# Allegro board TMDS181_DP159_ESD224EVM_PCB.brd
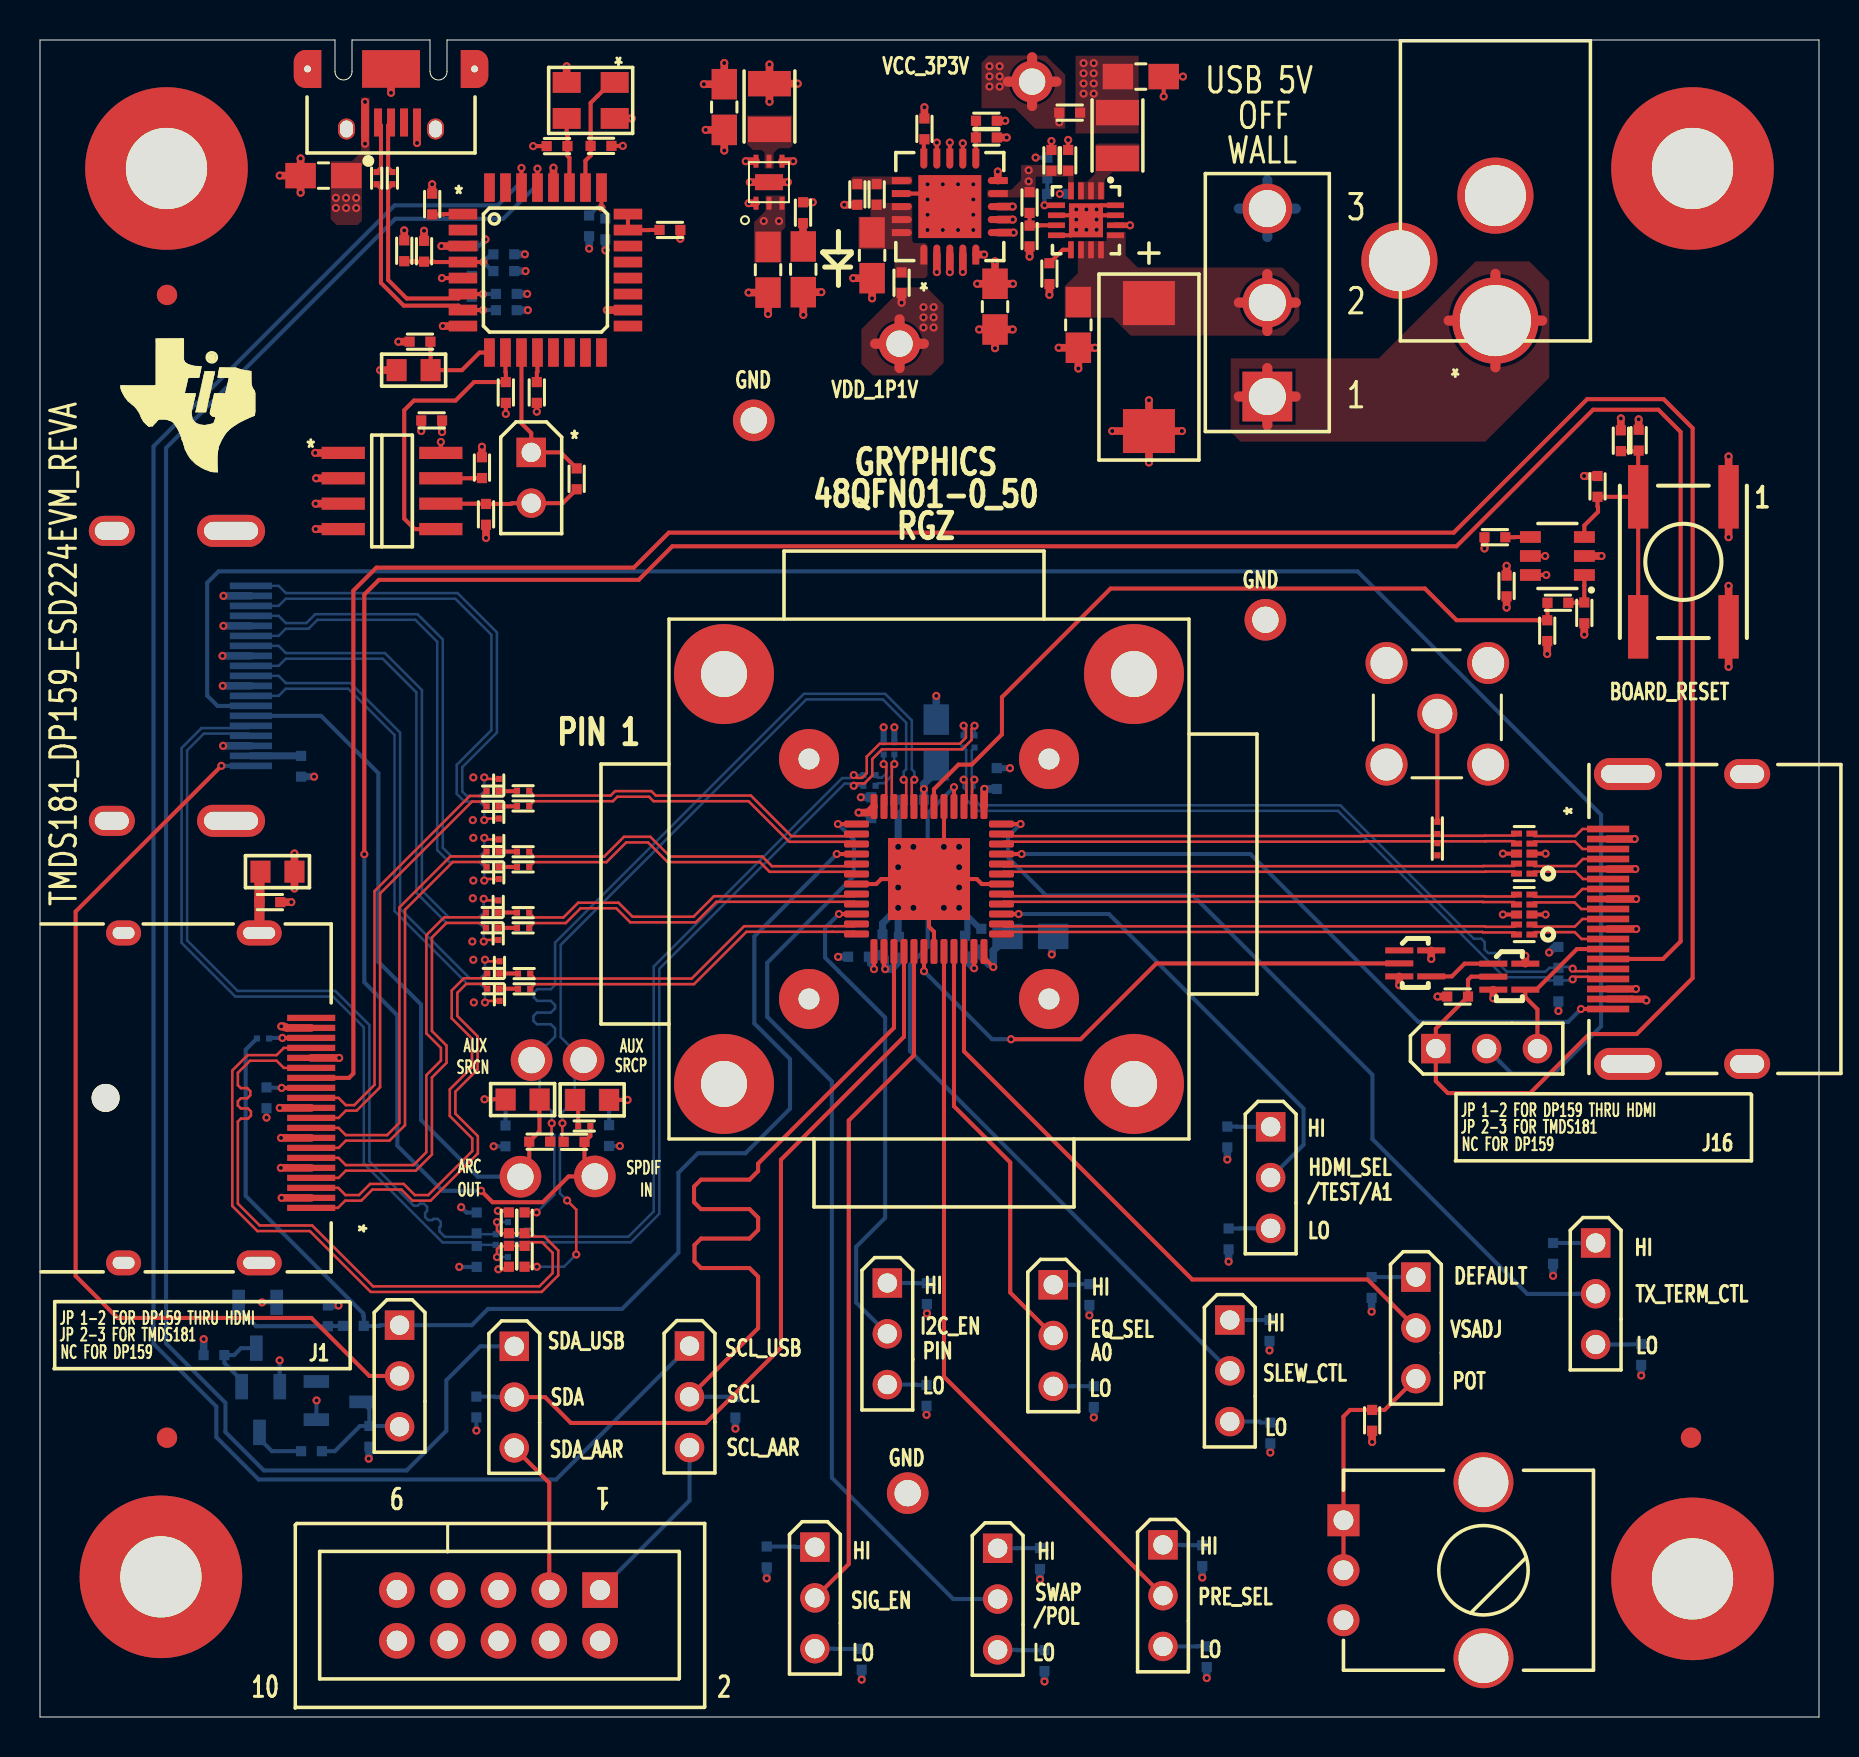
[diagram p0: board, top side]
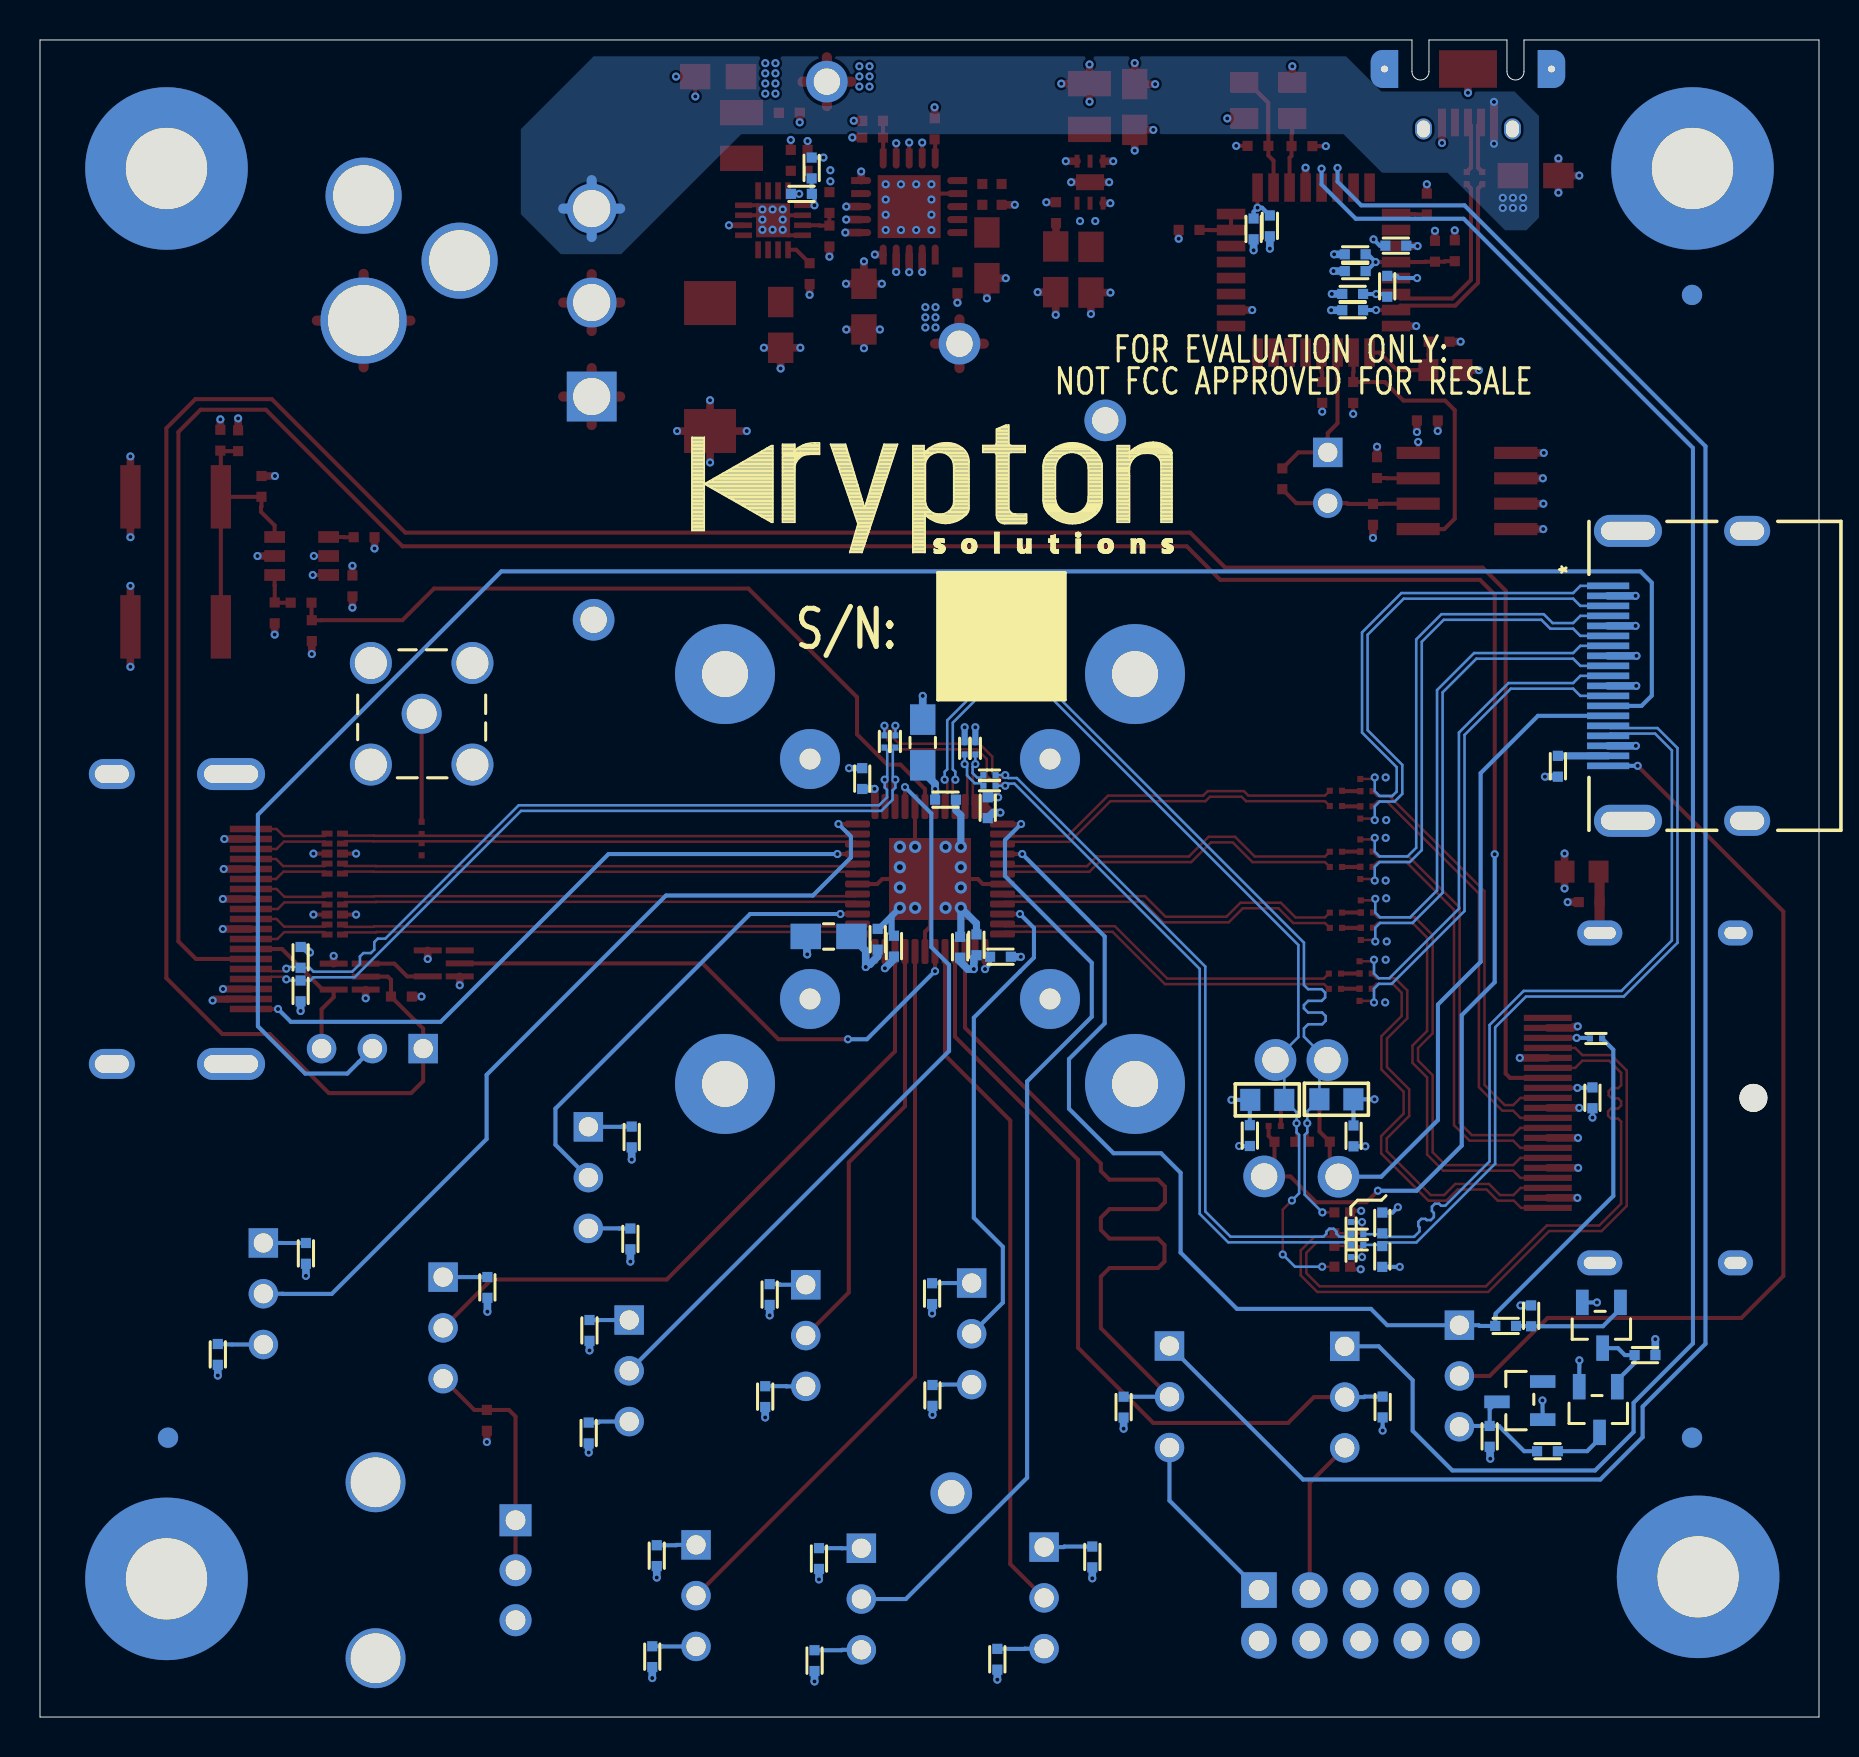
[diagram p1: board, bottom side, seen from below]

Outline 88.95 x 83.87 mm; copper layers: TOP, L2, L3, L4, L5, BOTTOM. Coordinates in mm from the lower left corner of the outline.
Outline path: 0,83.87 0,0 88.95,0 88.95,83.87 20.35,83.87 20.35,82.3 arc(19.93,81.87) 19.5,82.3 19.5,83.87 15.6,83.87 15.6,82.29 arc(15.18,81.87) 14.75,82.29 14.75,83.87 0,83.87

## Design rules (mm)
net group DIFFPAIR0: nets N16880319 N16880326
net group DIFFPAIR1: nets N16880333 N16880340
net group DIFFPAIR2: nets N16880347 N16880354
net group DIFFPAIR3: nets N16880361 N16880368
net group DIFFPAIR4: nets C_DPRX_LN3N C_DPRX_LN3P
net group DIFFPAIR5: nets C_DPRX_LN2N C_DPRX_LN2P
net group DIFFPAIR6: nets C_DPRX_LN1N C_DPRX_LN1P
net group DIFFPAIR7: nets C_DPRX_LN0N C_DPRX_LN0P
net group DIFFPAIR12: nets OUT_D2N OUT_D2P
net group DIFFPAIR13: nets OUT_D1N OUT_D1P
net group DIFFPAIR14: nets OUT_D0N OUT_D0P
net group DIFFPAIR15: nets OUT_CLKN OUT_CLKP
net group DIFFPAIR16: nets IN_D0N IN_D0P
net group DIFFPAIR17: nets IN_D1N IN_D1P
net group DIFFPAIR18: nets IN_D2N IN_D2P
net group DIFFPAIR19: nets IN_CLKN IN_CLKP
net group DIFFPAIR20: nets N16925972 N16925975
net group DIFFPAIR21: nets N16926008 N16926011
net group DIFFPAIR22: nets N16926002 N16926005
net group DIFFPAIR23: nets N16925996 N16925999
net group DIFFPAIR24: nets SCL_SRC SDA_SRC
net group DIFFPAIR25: nets HDMI_SCL_SRC HDMI_SDA_SRC
net group DIFFPAIR26: nets N16887471 N16913511
net group DIFFPAIR27: nets N16919318 N16919400
net group DIFFPAIR28: nets DP_SCL_SRC DP_SDA_SRC
net group DIFFPAIR29: nets AUX_SRCN/ARC_OUT AUX_SRCP/SPDIF_IN
net group DIFFPAIR30: nets SCL_SNK SDA_SNK
net group DIFFPAIR31: nets N17009600 N17009604
net group DIFFPAIR32: nets N17009637 N17009639
net group DIFFPAIR33: nets N17009633 N17009635
net group DIFFPAIR34: nets N17009643 N17009645
net group DIFF_PAIR 100 OHM_PH: nets EQ_SEL_A0 HDMI_SEL#_TEST_A1 I2C_EN_PIN OE PRE_SEL SCL_CTL_USB SDA_CTL_USB SIG_EN SLEW_CTL SWAP/POL TX_TERM_CTL VSADJ

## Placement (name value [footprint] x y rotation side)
C1  1 uF  [0603]  11.02 42.28 0 top
C2  0.1 uF  [0402]  24.23 24.72 270 top
C3  0.1 uF  [0402]  24.23 23.04 90 top
C4  1 uF  [0603]  24.98 30.89 180 bottom
C5  1 uF  [0603]  26.74 30.86 0 bottom
C6  1 uF  [0603]  24.98 30.88 180 top
C7  1 uF  [0603]  28.46 30.86 180 top
C8  10 uF  [0805]  44.81 48.74 90 bottom
C9  0.1 uF  [0402]  40.93 38.02 180 bottom
C10  0.1 uF  [0402]  43.67 45.88 180 bottom
C11  0.1 uF  [0201]  24.16 46.32 0 top
C12  0.1 uF  [0201]  24.16 45.56 0 top
C13  0.1 uF  [0201]  24.16 43.28 0 top
C14  0.1 uF  [0201]  24.16 42.51 0 top
C15  0.1 uF  [0201]  24.16 40.23 0 top
C16  0.1 uF  [0201]  24.16 39.47 0 top
C17  0.1 uF  [0402]  47.07 38.9 90 bottom
C18  0.1 uF  [0402]  41.56 45.48 90 bottom
C19  0.1 uF  [0402]  46.25 38.55 90 bottom
C20  10 uF  [0805]  49.52 39.04 0 bottom
C21  0.1 uF  [0402]  42.95 38.5 90 bottom
C22  0.01uF  [0402]  42.13 38.62 90 bottom
C23  0.1 uF  [0402]  47.84 46.93 90 bottom
C24  0.1 uF  [0201]  24.21 37.18 0 top
C25  0.1 uF  [0201]  24.21 36.42 0 top
C26  DNI_200nF  [0402]  75.36 54.33 270 top
C27  18 pF  [0402]  79.04 63.83 90 top
C28  220 pF  [0402]  72.75 59 180 top
C29  0.1 uF  [0402]  73.33 56.57 270 top
C30  330 uF  [7343]  55.45 70.71 270 top
C31  10 uF  [0805]  51.92 69.62 270 top
C32  22 uF  [0805]  55.04 82.04 0 top
C34  3300 pF  [0402]  50.47 72.19 270 top
C35  10 uF  [0805]  47.75 70.54 270 top
C36  10 uF  [0805]  41.61 73.1 270 top
C37  0.01uF  [0402]  47.32 78.99 0 top
C38  DNI  [0402]  44.22 79.43 90 top
C39  2.2 uF  [0805]  14.17 77.09 180 top
C40  0.1 uF  [0402]  27.46 74.57 90 bottom
C41  0.01uF  [0402]  28.27 74.42 90 bottom
C42  0.01uF  [0402]  21.16 73.58 180 bottom
C45  22 pF  [0402]  23.32 71.17 0 bottom
C46  0.1 uF  [0402]  23.19 73.15 180 bottom
C47  0.01uF  [0402]  23.19 72.31 180 bottom
C49  22 pF  [0402]  23.32 70.36 180 bottom
C50  33 pF  [0402]  28.05 78.58 0 top
C51  33 pF  [0402]  25.85 78.56 180 top
C52  1 uF  [0603]  17.83 67.36 0 top
C57  10 uF  [0805]  36.4 72.38 270 top
C58  2.2 uF  [0805]  34.21 80.52 270 top
C59  0.1 uF  [0402]  19.58 64.85 0 top
D1  Zener 6V  [SOT23_3]  13.82 14.87 0 bottom
D2  LED Green 0805  [0805]  38.16 72.4 270 top
J1  HDR3X1 M .1  [HDR_THVT_1X3_100]  17.98 19.6 0 top
J2  Display_Port_Connector_Sink_0  [CON_DP_SD-47272-001]  3.28 30.96 270 top
J3  HDR3X1 M .1  [HDR_THVT_1X3_100]  42.37 21.7 0 top
J4  HDR3X1 M .1  [HDR_THVT_1X3_100]  32.48 18.55 0 top
J5  Header 5x2 0.1" thru-hole  [CON_THVT_SHRD_2X5_100_M]  20.38 5.08 180 top
J6  HDR3X1 M .1  [HDR_THVT_1X3_100]  23.71 18.54 0 top
J7  HDR3X1 M .1  [HDR_THVT_1X3_100]  61.53 29.52 0 top
J8  HDR3X1 M .1  [HDR_THVT_1X3_100]  68.8 22 0 top
J9  2.1mm x 5.5mm  [PJ-202AH]  72.77 69.84 180 top
J10  HDR3X1 M .1  [HDR_THVT_1X3_100]  59.49 19.85 0 top
J11  HDR3X1 M .1  [HDR_THVT_1X3_100]  38.75 8.5 0 top
J12  HDR3X1 M .1  [HDR_THVT_1X3_100]  50.66 21.62 0 top
J13  USB Micro AB  [USB_MICRO_AB_MOLEX]  17.55 83.87 180 top
J14  HDR3X1 M .1  [HDR_THVT_1X3_100]  77.78 23.71 0 top
J15  HDR3X1 M .1  [HDR_THVT_1X3_100]  56.15 8.61 0 top
J16  HDR3X1 M .1  [HDR_THVT_1X3_100]  69.79 33.43 90 top
J17  HDR3X1 M .1  [HDR_THVT_1X3_100]  47.88 8.44 0 top
J18  5-1814832-1  [TE_5-1814832-1]  69.87 50.17 0 top
JP1  961102-6404-AR  [HDR_THVT_1X2_100]  24.56 63.25 0 top
L1  2.2 uH  [IND_1008]  53.87 79.1 90 top
L2  1 uH  [IND_1008]  36.47 80.54 270 top
LP1  LP  [TESTLOOP]  24.58 32.85 0 top
LP2  LP  [TESTLOOP]  27.18 32.86 180 top
LP3  LP  [TESTLOOP]  24.02 27.02 0 top
LP4  LP  [TESTLOOP]  27.74 27.04 180 top
LP5  LP  [TESTLOOP]  49.61 81.79 0 top
LP6  LP  [TESTLOOP]  42.98 68.68 0 top
LP7  LP  [TESTLOOP]  35.69 64.85 0 top
LP8  LP  [TESTLOOP]  61.27 54.87 0 top
LP9  LP  [TESTLOOP]  43.39 11.2 0 top
NOREF  -  [unnamed]  82.63 77.44 0 top
NOREF#2  -  [#2]  6.32 77.44 0 top
NOREF#3  -  [#2]  9.87 -39.35 0 top
NOREF#4  -  [#2]  0 0 0 top
NOREF#5  -  [unnamed]  6.05 7.01 0 top
NOREF#6  -  [#2]  0 83.47 0 top
NOREF#7  -  [#2]  82.63 6.91 0 top
NOREF#8  -  [#2]  0 0 0 top
NOREF#9  -  [#2]  6.32 77.44 0 top
NOREF#10  -  [unnamed]  82.63 6.91 0 top
NOREF#11  -  [#2]  4.01 62.26 0 top
NOREF#12  -  [#2]  88.95 0 90 top
NOREF#13  -  [unnamed]  6.35 13.97 0 top
NOREF#14  -  [unnamed]  6.35 71.12 0 top
NOREF#15  -  [unnamed]  6.32 77.44 0 top
NOREF#16  -  [#2]  6.32 77.44 90 top
NOREF#17  -  [unnamed]  82.55 13.97 0 top
NOREF#18  -  [unnamed]  6.35 71.12 180 bottom
NOREF#19  -  [unnamed]  6.35 13.97 180 bottom
NOREF#20  -  [#2]  51.04 54.05 180 bottom
NOREF#21  -  [unnamed]  82.55 13.97 180 bottom
NOREF#22  -  [#2]  56.4 58.17 180 bottom
NOREF#23  -  [#2]  61.97 43.18 180 bottom
P1  HDMI_IN  [CON_HDMI_SD-47151-001]  10.54 52.07 90 bottom
P2  HDMI_OUT  [CON_HDMI_SD-47151-001]  78.41 39.91 90 top
Q1  FDV301N  [SOT23_3]  9.93 20.73 270 bottom
Q2  FDV301N  [SOT23_3]  10.08 16.52 270 bottom
R5  100  [0402]  15.67 19.56 180 bottom
R10  1K  [0402]  16.47 14.04 270 bottom
R11  1K  [0402]  8.7 18.1 180 bottom
R12  100K  [0402]  14.39 20.06 270 bottom
R13  10  [0402]  13.58 13.29 0 bottom
R14  0  [0201]  22.94 46.61 90 top
R15  0  [0201]  22.94 45.24 270 top
R16  2K  [0402]  21.84 23.03 270 bottom
R17  2K  [0402]  21.83 24.71 90 bottom
R18  0  [0201]  22.94 43.59 90 top
R19  0  [0201]  22.94 42.21 270 top
R20  0  [0201]  22.91 40.54 90 top
R21  0  [0201]  22.91 39.17 270 top
R22  0  [0201]  22.97 37.49 90 top
R23  0  [0201]  22.97 36.12 270 top
R24  0  [0201]  23.09 23.61 180 bottom
R25  0  [0201]  23.09 24.15 180 bottom
R27  100K  [0402]  11.33 30.97 270 bottom
R28  2K  [0402]  23.44 24.72 90 top
R29  2K  [0402]  23.44 23.04 270 top
R30  1M  [0402]  11.49 40.75 180 top
R31  0  [0201]  23.4 23.31 270 bottom
R32  0  [0201]  23.4 24.45 90 bottom
R33  0  [0201]  11.15 33.93 0 bottom
R34  0  [0201]  27.21 29.56 180 top
R35  54.9  [0402]  23.27 29.06 90 bottom
R36  75  [0402]  28.46 29.08 90 bottom
R45  2K  [0402]  75.92 37.99 90 bottom
R46  2K  [0402]  75.92 36.31 270 bottom
R56  27K  [0402]  70.88 36.03 180 top
R57  64.9K  [0402]  44.35 21.17 90 bottom
R58  2K  [0402]  34.77 15.5 90 bottom
R59  2K  [0402]  21.82 15.5 90 bottom
R60  64.9K  [0402]  44.33 16.08 270 bottom
R61  64.9K  [0402]  50 7.92 90 bottom
R62  64.9K  [0402]  50.22 2.82 270 bottom
R63  64.9K  [0402]  58.11 8.07 90 bottom
R64  64.9K  [0402]  58.34 3.02 270 bottom
R65  64.9K  [0402]  61.48 19.33 90 bottom
R66  64.9K  [0402]  59.37 29.01 90 bottom
R67  64.9K  [0402]  61.52 14.2 270 bottom
R68  64.9K  [0402]  52.47 21.13 90 bottom
R69  64.9K  [0402]  59.43 23.91 270 bottom
R70  64.9K  [0402]  52.69 16.02 270 bottom
R71  64.9K  [0402]  36.34 8 90 bottom
R72  64.9K  [0402]  75.66 23.19 90 bottom
R73  64.9K  [0402]  41.08 2.89 270 bottom
R74  64.9K  [0402]  80.06 18.13 270 bottom
R75  6.98K  [0402]  66.58 21.48 90 bottom
R76  PTV09 10K POT  [VAR_RES_THVT_PTV09A-1_123]  65.17 7.34 270 top
R77  0  [0402]  75.9 55.73 0 top
R78  10K  [0402]  77.22 55.22 90 top
R79  4.7K OHM  [0402]  79.93 63.86 270 top
R80  0  [0402]  77.88 61.54 90 top
R81  100K  [0402]  51.41 77.85 270 top
R82  499  [0402]  38.15 75.23 90 top
R83  0  [0402]  49.48 75.74 90 top
R84  0  [0402]  51.49 80.24 0 top
R85  750K  [0402]  50.37 77.47 90 bottom
R86  240K  [0402]  50.88 76.17 180 bottom
R87  DNI  [0402]  50.57 77.85 270 top
R88  4.7K OHM  [0402]  47.32 79.83 180 top
R89  0  [0402]  43.08 71.73 90 top
R90  2.21K  [0402]  41.83 76.15 270 top
R91  4.42K OHM  [0402]  40.87 76.15 90 top
R92  DNI  [0402]  18.21 73.33 90 top
R93  DNI  [0402]  19.2 73.3 270 top
R94  1.5K  [0402]  21.59 71.55 270 bottom
R95  33  [0201]  16.83 76.96 90 top
R96  33  [0201]  17.62 76.96 90 top
R98  10K  [0402]  31.5 74.37 180 top
R99  1K  [0402]  23.29 66.24 90 top
R100  1K  [0402]  22.3 60.15 90 top
R101  1K  [0402]  19.61 75.67 90 top
R102  10K  [0402]  24.84 66.24 90 top
R103  15K  [0402]  19 68.78 0 top
R104  0  [0402]  13.06 47.55 90 bottom
R105  0  [0201]  22.63 46.3 180 top
R106  0  [0201]  22.63 45.54 180 top
R107  0  [0201]  22.63 43.28 180 top
R108  0  [0201]  22.61 40.23 180 top
R109  0  [0201]  22.67 37.19 180 top
R110  0  [0201]  22.63 42.52 180 top
R111  0  [0201]  22.61 39.47 180 top
R112  0  [0201]  22.67 36.42 180 top
R113  DNI  [0402]  26.71 28.77 180 top
R114  DNI  [0402]  24.98 28.77 0 top
R115  47K  [0402]  66.61 14.84 270 top
R120  DNI  [0402]  49.48 74.07 270 top
R121  1K  [0402]  22.1 62.48 90 top
R122  0  [0402]  26.83 61.92 270 top
R123  0  [0201]  69.87 44.47 270 top
R124  DNI  [0201]  69.87 43.4 90 top
R125  0  [0201]  42.72 48.45 90 bottom
R126  0  [0201]  42.18 48.45 90 bottom
R127  0  [0201]  46.73 48.79 90 bottom
R128  0  [0201]  46.18 48.79 90 bottom
R129  0  [0201]  41.48 46.57 180 bottom
R130  0  [0201]  41.48 47.11 180 bottom
SW1  PB_SWITCH  [SW_MOM_2NO]  82.17 57.77 180 top
SW2  3POS - SPDT  [SW_THVT_SPDT_3_185P]  61.37 70.74 0 top
U1  DP159RGZ  [RGZ48_GRYPHICS_48QFN07-0P5]  44.45 41.91 0 top
U2  SN74CBT1G125  [DCK_R-PDSO-G5]  73.47 37.03 0 top
U3  TPS3808  [DBV_R-PDSO-G6]  75.87 58.06 180 top
U4  TPS62150A  [RGT_QFN-16]  52.3 74.85 270 top
U5  TPS74401RGWT_1  [QFN_20_203X203_26]  45.49 75.54 90 top
U6  TPS61240  [DRV_S-PWSON-N6]  36.45 76.76 90 top
U7  TUSB3410  [PQFP_32_7P2X7P2_P8MM]  25.27 72.36 0 top
U8  24LC256  [SOIC_8_197X157_50]  17.6 61.32 0 top
U9  SN74AUP1G04  [DCK_R-PDSO-G5]  68.76 37.69 0 top
U10  DQA  [SON50P100X250X55-10]  74.21 43.18 180 top
U11  DQA  [SON50P100X250X55-10]  74.21 40.13 180 top
Y1  12 MHz  [XTAL_4_SM_126X98]  27.53 80.85 180 top

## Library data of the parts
C1 C4-C7 C52 = LMK107B7105KA-T
C2 C3 C9 C10 C17-C19 C21 C23 C29 C40 C46 C59 = CC0402KRX5R6BB104
C8 C20 C31 C35 C36 C57 = C2012X5R1E106K125AB
C11-C16 C24 C25 = GRM033R61E104KE14J
C22 C37 C41 C42 C47 = GRM155R71H103JA88D
C26 = LMK105BJ224KV-F
C27 = 04025A180JAT2A
C28 = UMK105B7221KV-F
C30 = T495X337K010ATE060
C32 = C0805C226K9PAC7800
C34 = CL05B332KB5NNNC
C38 = CAP NP
C39 C58 = EMK212BJ225KG-T
C45 C49 = GRM1555C1H220JA01D
C50 C51 = GRM1555C1H330JA01D
D1 = MMBZ5233B-7-F
D2 = LTST-C171GKT
J1 J3 J4 J6-J8 J10-J12 J14-J17 = 961103-6404-AR
J2 = 47272-0001
J5 = N2510-6002-RB
J9 = BNC_2
J13 = 47590-0001
J18 = 5-1814832-1
JP1 = 961102-6404-AR
L1 = VLS252010ET-2R2M
L2 = NLCV25T-1R0M-EFR
LP1-LP9 = 151-103-RC
P1 P2 = 47151-0001
Q1 Q2 = FDV301N
R5 = RC0402FR-07100RL
R10 R11 R99-R101 R121 = RC0402JR-071KL
R12 R27 R81 = RC0402JR-07100KL
R13 = RC0402JR-0710RL
R14 R15 R18-R25 R31-R34 R105-R112 R123-R130 = ERJ-1GN0R00C
R16 R17 R28 R29 R45 R46 R58 R59 = RC0402JR-072KL
R30 = RC0402FR-071ML
R35 = ERA-2AEB54R9X
R36 = RC0402JR-0775RL
R56 = ERA-2AEB273X
R57 R60-R74 = RC0402FR-0764K9L
R75 = ERA-2AEB6981X
R76 = POT
R77 R80 R83 R84 R89 R104 R122 = ERJ-2GE0R00X
R78 R98 R102 = RC0402JR-0710KL
R79 R88 = RC0402JR-074K7L
R82 = CRCW0402499RDHEDP
R85 = CRCW0402750KJNED
R86 = CRCW0402240KJNED
R87 R92 R93 R113 R114 R120 = R
R90 = ERA-2APB2211X
R91 = RMCF0402FT4K42
R94 = RC0402JR-071K5L
R95 R96 = RC0201JR-0733RL
R103 = RC0402JR-0715KL
R115 = ERA-2APB473X
SW1 = PB_SWITCH_0
SW2 = SW_SLIDE_SPDT2
U1 = DP159RGZ_6
U2 = SN74CBT1G125
U3 = TPS3808DBV
U4 = TPS62150A
U5 = TPS74401RGWT_1
U6 = TPS61420
U7 = TUSB3410_3
U8 = I2C_0
U9 = SN74AUP1G04
U10 U11 = DQA
Y1 = CRYSTAL14_0

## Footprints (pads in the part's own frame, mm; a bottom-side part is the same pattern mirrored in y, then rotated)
0201
  rect 0.305x0.305 smd: 1(-0.305,0) 2(0.305,0)
0402
  rect 0.508x0.508 smd: 1(-0.521,0) 2(0.521,0)
0603
  rect 1x1.1 smd: 1(0,0) 2(1.7,0)
0805
  rect 1.524x1.27 smd: 1(-1.143,0) 2(1.143,0)
7343
  rect 2.2x2.6 smd: 1(0,0) 2(6.4,0)
CON_DP_SD-47272-001
  round 1.4 hole 1.4 unplated: (0,0)
  rect 0.31x2.4 smd: 1(5.5,10.28) 2(5,10.28) 3(4.5,10.28) 4(4,10.28) 5(3.5,10.28) 6(3,10.28) 7(2.5,10.28) 8(2,10.28) 9(1.5,10.28) 10(1,10.28) 11(0.5,10.28) 12(0,10.28) 13(-0.5,10.28) 14(-1,10.28) 15(-1.5,10.28) 16(-2,10.28) 17(-2.5,10.28) 18(-3,10.28) 19(-3.5,10.28) 20(-4,10.28)
  oval 1.25x2.25 hole 0.6x1.6: 21(-8.25,7.68) 24(8.25,7.68)
  oval 1.25x1.75 hole 0.6x1.1: 22(-8.25,0.9) 23(8.25,0.9)
CON_HDMI_SD-47151-001
  rect 0.33x2.11 smd: 1(4.501,0) 2(4,0) 3(3.5,0) 4(3,0) 5(2.499,0) 6(1.999,0) 7(1.501,0) 8(1.001,0) 9(0.5,0) 10(0,0) 11(-0.5,0) 12(-1.001,0) 13(-1.501,0) 14(-1.999,0) 15(-2.499,0) 16(-3,0) 17(-3.5,0) 18(-4,0) 19(-4.501,0)
  oval 1.6x3.4 hole 0.9x2.7: 20(-7.248,-0.99) 21(7.25,-0.99)
  oval 1.5x2.3 hole 0.9x1.7: 22(7.25,-6.951) 23(-7.248,-6.951)
CON_THVT_SHRD_2X5_100_M
  rect 1.778x1.778 hole 1.016: 1(-7.62,-1.27)
  round 1.778 hole 1.016: 2(-7.62,1.27) 3(-5.08,-1.27) 4(-5.08,1.27) 5(-2.54,-1.27) 6(-2.54,1.27) 7(0,-1.27) 8(0,1.27) 9(2.54,-1.27) 10(2.54,1.27)
DBV_R-PDSO-G6
  rect 1.041x0.584 smd: 1(-1.35,0.95) 2(-1.35,0) 3(-1.35,-0.95) 4(1.35,-0.95) 5(1.35,0) 6(1.35,0.95)
DCK_R-PDSO-G5
  rect 1.4x0.3 smd: 1(-0.8,0.65) 2(-0.8,0) 3(-0.8,-0.65) 4(0.8,-0.65) 5(0.8,0.65)
DRV_S-PWSON-N6
  rect 0.65x0.25 smd: 1(-1.05,0.65) 2(-1.05,0) 3(-1.05,-0.65) 4(1.05,-0.65) 5(1.05,0) 6(1.05,0.65)
  rect 0.8x1.4 smd: 7(0,0)
HDR_THVT_1X2_100
  rect 1.473x1.473 hole 0.965: 1(0,0)
  round 1.473 hole 0.965: 2(0,-2.54)
HDR_THVT_1X3_100
  rect 1.473x1.473 hole 0.965: 1(0,0)
  round 1.473 hole 0.965: 2(0,-2.54) 3(0,-5.08)
IND_1008
  rect 1.27x2.146 smd: 1(-1.143,0) 2(1.143,0)
PJ-202AH
  round 4.318 hole 3.556: 1(0,0)
  round 3.81 hole 3.048: 2(4.801,-2.997) 3(0,-6.248)
PQFP_32_7P2X7P2_P8MM
  rect 1.422x0.533 smd: 1(-4.125,2.8) 2(-4.125,2) 3(-4.125,1.2) 4(-4.125,0.4) 5(-4.125,-0.4) 6(-4.125,-1.2) 7(-4.125,-2) 8(-4.125,-2.8) 17(4.125,-2.8) 18(4.125,-2) 19(4.125,-1.2) 20(4.125,-0.4) 21(4.125,0.4) 22(4.125,1.2) 23(4.125,2) 24(4.125,2.8)
  rect 0.533x1.422 smd: 9(-2.8,-4.125) 10(-2,-4.125) 11(-1.2,-4.125) 12(-0.4,-4.125) 13(0.4,-4.125) 14(1.2,-4.125) 15(2,-4.125) 16(2.8,-4.125) 25(2.8,4.125) 26(2,4.125) 27(1.2,4.125) 28(0.4,4.125) 29(-0.4,4.125) 30(-1.2,4.125) 31(-2,4.125) 32(-2.8,4.125)
QFN_20_203X203_26
  custom 0.088x0.088 smd: 1(-2.4,1.3) 2(-2.4,0.65) 3(-2.4,0) 4(-2.4,-0.65) 5(-2.4,-1.3) 6(-1.3,-2.4) 7(-0.65,-2.4) 8(0,-2.4) 9(0.65,-2.4) 10(1.3,-2.4) 11(2.4,-1.3) 12(2.4,-0.65) 13(2.4,0) 14(2.4,0.65) 15(2.4,1.3) 16(1.3,2.4) 17(0.65,2.4) 18(0,2.4) 19(-0.65,2.4) 20(-1.3,2.4)
  rect 3.15x3.15 smd: 21(0,0)
RGT_QFN-16
  rect 0.85x0.28 smd: 1(-1.475,0.75) 2(-1.475,0.25) 3(-1.475,-0.25) 4(-1.475,-0.75) 9(1.475,-0.75) 10(1.475,-0.25) 11(1.475,0.25) 12(1.475,0.75)
  rect 0.28x0.85 smd: 5(-0.75,-1.475) 6(-0.25,-1.475) 7(0.25,-1.475) 8(0.75,-1.475) 13(0.75,1.475) 14(0.25,1.475) 15(-0.25,1.475) 16(-0.75,1.475)
  rect 1.7x1.7 smd: 17(0,0)
RGZ48_GRYPHICS_48QFN07-0P5
  round 5 hole 2.3: (-10.25,10.25) (-10.25,-10.25) (10.25,10.25) (10.25,-10.25)
  round 3 hole 1.05 unplated: (-6,6) (-6,-6) (6,6) (6,-6)
  custom 0.088x0.088 smd: 1(-3.625,2.75) 2(-3.625,2.25) 3(-3.625,1.75) 4(-3.625,1.25) 5(-3.625,0.75) 6(-3.625,0.25) 7(-3.625,-0.25) 8(-3.625,-0.75) 9(-3.625,-1.25) 10(-3.625,-1.75) 11(-3.625,-2.25) 12(-3.625,-2.75) 13(-2.75,-3.625) 14(-2.25,-3.625) 15(-1.75,-3.625) 16(-1.25,-3.625) 17(-0.75,-3.625) 18(-0.25,-3.625) 19(0.25,-3.625) 20(0.75,-3.625) 21(1.25,-3.625) 22(1.75,-3.625) 23(2.25,-3.625) 24(2.75,-3.625) 25(3.625,-2.75) 26(3.625,-2.25) 27(3.625,-1.75) 28(3.625,-1.25) 29(3.625,-0.75) 30(3.625,-0.25) 31(3.625,0.25) 32(3.625,0.75) 33(3.625,1.25) 34(3.625,1.75) 35(3.625,2.25) 36(3.625,2.75) 37(2.75,3.625) 38(2.25,3.625) 39(1.75,3.625) 40(1.25,3.625) 41(0.75,3.625) 42(0.25,3.625) 43(-0.25,3.625) 44(-0.75,3.625) 45(-1.25,3.625) 46(-1.75,3.625) 47(-2.25,3.625) 48(-2.75,3.625)
  rect 4.1x4.1 smd: 49(0,0)
SOIC_8_197X157_50
  rect 2.159x0.61 smd: 1(-2.44,1.905) 2(-2.44,0.635) 3(-2.44,-0.635) 4(-2.44,-1.905) 5(2.44,-1.905) 6(2.44,-0.635) 7(2.44,0.635) 8(2.44,1.905)
SON50P100X250X55-10
  rect 0.55x0.3 smd: 1(-0.385,1) 2(-0.385,0.5) 4(-0.385,-0.5) 5(-0.385,-1) 6(0.385,-1) 7(0.385,-0.5) 9(0.385,0.5) 10(0.385,1)
  rect 0.55x0.4 smd: 3(-0.385,0) 8(0.385,0)
SOT23_3
  rect 1.27x0.635 smd: 1(0,0) 2(0,-1.905) 3(2.286,-0.889)
SW_MOM_2NO
  rect 1.016x3.175 smd: 1(-2.261,-3.251) 2(-2.261,3.251) 3(2.261,-3.251) 4(2.261,3.251)
SW_THVT_SPDT_3_185P
  rect 2.489x2.489 hole 1.854: 1(0,-4.7)
  round 2.489 hole 1.854: 2(0,0) 3(0,4.7)
TE_5-1814832-1
  round 2 hole 1.5: 1(0,0)
  round 2.1 hole 1.6: 2(2.54,2.54) 3(-2.54,2.54) 4(-2.54,-2.54) 5(2.54,-2.54)
TESTLOOP
  round 2.083 hole 1.321: 1(0,0)
unnamed
  round 8.128 hole 4.064: (0,0)
USB_MICRO_AB_MOLEX
  rect 0.4x1.4 smd: 1(1.3,4.125) 2(0.65,4.125) 3(0,4.125) 4(-0.65,4.125) 5(-1.3,4.125)
  oval 0.85x1.05 hole 0.65x0.85: 6(-2.225,4.45) 7(2.225,4.45)
  rect 2.896x1.88 smd: 8(0,1.45)
  custom 0.344x0.344 hole 0.6x1.3: 9(-4.175,1.45) 10(4.175,1.45)
VAR_RES_THVT_PTV09A-1_123
  round 2.997 hole 2.489: (-4.4,7) (4.4,7)
  rect 1.6x1.6 hole 0.991: 1(-2.5,0)
  round 1.6 hole 0.991: 2(0,0) 3(2.5,0)
XTAL_4_SM_126X98
  rect 1.397x1.041 smd: 1(-1.2,-0.9) 2(1.2,-0.9) 3(1.2,0.9) 4(-1.2,0.9)

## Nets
+1V8: C46.2 C47.2 R92.1 R93.2 U7.4(VDD1V8)
GND: C1.2 C8.2 C9.2 C10.2 C17.2 C18.2 C19.2 C20.2 C21.2 C22.2 C23.2 C26.2 C27.2 C28.2 C29.2 C30.2 C31.2 C32.2 C34.2 C35.2 C36.2 C37.2 C38.2 C39.2 C40.1 C41.1 C42.1 C45.2 C46.1 C47.1 C49.1 C50.2 C51.2 C52.1 C57.2 C58.2 C59.1 D1.1 D2.2(K) J2.2(GND1) J2.5(GND2) J2.8(GND3) J2.11(GND4) J2.16(GND6) J2.19(DP_PWR_RTN) J5.2(6) J5.10 J9.2(S) J9.3(SW) J13.5(GND) J13.6(S1) J13.7(S2) J13.8(S3) J13.9(S4) J13.10(S5) J18.2(SHIELD1) J18.3(SHIELD2) J18.4(SHIELD3) J18.5(SHIELD4) LP7.1 LP8.1 LP9.1 P1.2 P1.5 P1.8 P1.11 P1.17 P1.20(CASE1) P1.21(CASE2) P1.22(CASE3) P1.23(CASE4) P2.2 P2.5 P2.8 P2.11 P2.17 P2.20(CASE1) P2.21(CASE2) P2.22(CASE3) P2.23(CASE4) Q1.2(S) Q2.2(S) R12.1 R30.1 R35.1 R36.1 R60.2 R62.2 R64.2 R67.2 R69.2 R70.2 R73.2 R74.2 R75.1 R76.3(B) R86.1 R91.1 R93.1 R101.2 R115.2 R120.2 R121.2 R125.2 R126.2 SW1.1(A) SW1.2(A_) U1.7(GND1) U1.19(GND2) U1.30(GND3) U1.41(GND4) U1.49(PAD) U2.3(GND) U3.2(GND) U4.6(AGND) U4.8(DEF) U4.15(PGND1) U4.16(PGND2) U4.17(PAD) U5.2(NC1) U5.3(NC2) U5.4(NC3) U5.12(GND) U5.13(NC4) U5.14(NC5) U5.17(NC6) U5.21(PAD) U6.1(GND) U6.7(PAD) U7.8(GND1) U7.18(GND2) U7.28(GND3) U8.1(A0) U8.2(A1) U8.3(A2) U8.4(VSS) U9.3(GND) U10.3 U10.8 U11.3 U11.8 Y1.2 Y1.4
VCC_3P3V: C8.1 C9.1 C10.1 C29.1 LP5.1 R57.1 R58.1 R59.1 R61.1 R63.1 R65.1 R66.1 R68.1 R71.1 R72.1 R78.1 R84.1 U1.13(VCC1) U1.43(VCC2) U3.5(SENSE) U3.6(VDD)
VDD_1P1V: C17.1 C18.1 C19.1 C20.1 C21.1 C22.1 C23.1 LP6.1 R89.1 U1.14(VDD1) U1.23(VDD2) U1.24(VDD3) U1.37(VDD4) U1.48(VDD5)
ARC_OUT: C6.1 LP3.1 P1.14 R114.1
AUX_SRCN/ARC_OUT: C2.1 C4.1 LP1.1 R114.2 U1.44(AUX_SRCN/ARC_OUT)
AUX_SRCP/SPDIF_IN: C3.1 C5.1 LP2.1 R113.2 U1.45(AUX_SRCP/SPDIF_IN)
BOARD_1P1V: C36.1 R89.2 R90.2 U5.1(OUT1) U5.18(OUT4) U5.19(OUT3) U5.20(OUT2)
BOARD_3P3V: C32.1 C35.1 C40.2 C41.2 C42.2 C58.1 C59.2 L1.2 L2.1 R27.2 R28.2 R29.2 R56.2 R79.1 R81.1 R84.2 R85.2 R87.1 R88.1 R92.2 R98.1 R99.1 R100.1 R102.1 R103.1 U4.14(VOS) U5.5(IN1) U5.6(IN2) U5.7(IN3) U5.8(IN4) U5.10(BIAS) U6.4(EN) U6.6(VIN) U7.3(VCC1) U7.25(VCC2) U8.8(VCC) U9.5(VCC)
BOARD_5V: C57.1 P2.18 R10.2 R11.2 R16.2 R17.2 R45.2 R46.2 R82.2 R104.1 U2.5(VCC) U6.2(VOUT) U6.3(FB)
BOARD_IN: C30.1 C31.1 SW2.2 U4.10(AVIN) U4.11(PVIN1) U4.12(PVIN2) U4.13(EN)
C_DPRX_LN0N: J2.10(ML_0N) R106.2
C_DPRX_LN0P: J2.12(ML_0P) R105.2
C_DPRX_LN1N: J2.7(ML_1N) R110.2
C_DPRX_LN1P: J2.9(ML_1P) R107.2
C_DPRX_LN2N: J2.4(ML_2N) R111.2
C_DPRX_LN2P: J2.6(ML_2P) R108.2
C_DPRX_LN3N: J2.1(ML_3N) R112.2
C_DPRX_LN3P: J2.3(ML_3P) R109.2
CEC_EN: U1.18(CEC_EN/NC) U9.2(A)
CEC_SRC: J2.14(DP_CEC (GND)) J16.1 R56.1 U2.2(A)
DP_CAD: J2.13(CAD (GND)) R27.1
DP_SCL_SRC: C3.2 J2.15(AUX_P (SCL)) R29.1 R31.2
DP_SDA_SRC: C2.2 J2.17(AUX_N (SDA)) R28.1 R32.2
DPRX_GND: C1.1 J2.21(GND7) J2.22(GND8) J2.23(GND9) J2.24(GND10) R30.2
EN1P2: C37.1 R88.2 U5.11(EN)
EQ_SEL_A0: J12.2 U1.21(EQ_SEL/A0)
EQ_SEL_HI: J12.1 R68.2
EQ_SEL_LO: J12.3 R70.1
FB_1PT2V: R90.1 R91.2 U5.16(FB)
FB_3PT3V: R85.1 R86.2 U4.5(FB)
HDMI_CEC_SNK: J16.3 P2.13 U2.4(B)
HDMI_CEC_SRC: J16.2 P1.13
HDMI_IN_5V: P1.18 R104.2
HDMI_SCL_SRC: P1.15 R16.1 R24.2
HDMI_SDA_SRC: P1.16 R17.1 R25.2
HDMI_SEL#_TEST_A1: J7.2 U1.27(HDMI_SEL#/A1)
HPD_SNK: P2.19 U1.33(HPD_SNK)
HPD_SRC: J1.1 R5.1 R33.1 U1.4(HPD_SRC)
HPD_SRC_CONN: D1.3 J1.3 R10.1 R13.2
HPD_SRC_HDMI_RX_CONN: J1.2 P1.19
I2C_EN_HI: J3.1 R57.2
I2C_EN_LO: J3.3 R60.1
I2C_EN_PIN: J3.2 U1.10(I2C_EN/PIN)
IN_CLKN: C25.1 R23.1 R112.1
IN_CLKP: C24.1 R22.1 R109.1
IN_D0N: C16.1 R21.1 R111.1
IN_D0P: C15.1 R20.1 R108.1
IN_D1N: C14.1 R19.1 R110.1
IN_D1P: C13.1 R18.1 R107.1
IN_D2N: C12.1 R15.1 R106.1
IN_D2P: C11.1 R14.1 R105.1
OE: C26.1 R77.1 U1.42(OE)
OUT_CLKN: P2.12 U11.1
OUT_CLKP: P2.10 U11.2
OUT_D0N: P2.9 U11.4
OUT_D0P: P2.7 U11.5
OUT_D1N: P2.6 U10.1
OUT_D1P: P2.4 U10.2
OUT_D2N: P2.3 U10.4
OUT_D2P: P2.1 U10.5
PB_MANUAL_RESET: C27.1 R79.2 R80.1 SW1.3(B_) SW1.4(B) U3.3(MR#)
PRE_SEL: J15.2 U1.20(PRE_SEL)
PRE_SEL_HI: J15.1 R63.2
PRE_SEL_LO: J15.3 R64.1
PWRIN_SW: J9.1(T) SW2.1
REG_PG: R80.2 R81.2 R83.2 R87.2 U4.4(PG) U5.9(PG)
RSTIN: C52.2 R103.2 U7.9(\\R\E\S\E\T\)
SCL_CTL: J4.2 R58.2 U1.15(SCL_CTL)
SCL_CTL_USB: J4.1 U7.30(P3_3)
SCL_SNK: P2.15 R45.1 R127.1 U1.38(SCL_SNK)
SCL_SRC: R24.1 R31.1 R127.2 R129.2
SDA_CTL: J6.2 R59.2 U1.16(SDA_CTL)
SDA_CTL_USB: J6.1 U7.29(P3_4)
SDA_SNK: P2.16 R46.1 R128.1 U1.39(SDA_SNK)
SDA_SRC: R25.1 R32.1 R128.2 R130.2
SIG_EN: J11.2 U1.17(SIG_EN)
SIG_EN_HI: J11.1 R71.2
SIG_EN_LO: J11.3 R73.1
SLEW_CTL: J10.2 U1.40(SLEW_CTL)
SLEW_CTL_HI: J10.1 R65.2
SLEW_CTL_LO: J10.3 R67.1
SPDIF_IN: LP4.1 P2.14 R34.1 R113.1
SS1P2: C38.1 U5.15(SS)
SWAP/POL: J17.2 U1.1(SWAP/POL)
SWAP_POL_HI: J17.1 R61.2
SWAP_POL_LO: J17.3 R62.1
TPS3808_CT: C28.1 U3.4(CT)
TX_TERM_CTL: J14.2 U1.36(TX_TERM_CTL)
TX_TERM_CTL_HI: J14.1 R72.2
TX_TERM_CTL_LO: J14.3 R74.1
USB_5V: C39.1 J13.1(VBUS) SW2.3
VSADJ: J8.2 U1.22(VSADJ)
X1: C51.1 U7.27(X1/CLKI) Y1.3
X2: C50.1 U7.26(X2) Y1.1
N16782838: R77.2 R78.2 U3.1(RESET#)
N16869116: R125.1 R129.1 U1.46(SCL_SRC)
N16869122: R126.1 R130.1 U1.47(SDA_SRC)
N16874758: J7.1 R66.2
N16874763: J7.3 R69.1
N16880319: P1.1 R14.2
N16880326: P1.3 R15.2
N16880333: P1.4 R18.2
N16880340: P1.6 R19.2
N16880347: P1.7 R20.2
N16880354: P1.9 R21.2
N16880361: P1.10 R22.2
N16880368: P1.12 R23.2
N16881139: J5.3(2) J6.3
N16881148: J4.3 J5.1
N16883754: J8.1 R75.2
N16883759: J8.3 R76.1(A) R76.2(WIPER) R115.1
N16887406: R102.2 U7.12(\\W\A\K\E\U\P\)
N16887471: J13.3(DP) R96.2
N16892757: Q1.1(G) R5.2 R12.2
N16892765: Q1.3(D) Q2.1(G) R11.1
N16892877: Q2.3(D) R13.1
N16906083: C5.2 C7.1 R36.2
N16910161: C4.2 C6.2 R35.2
N16913511: J13.2(DM) R95.2
N16916452: JP1.1 R122.1 U7.11(SCL)
N16916458: JP1.2 R100.2 R122.2 U8.6(SCL)
N16916991: R99.2 U7.10(SDA) U8.5(SDA)
N16919313: R94.1 U7.5(PUR)
N16919318: C45.1 R94.2 R96.1 U7.6(DP0)
N16919400: C49.2 R95.1 U7.7(DM0)
N16919998: R101.1 U7.1(\\V\R\E\G\E\N\)
N16925972: C11.2 U1.2(IN_D2P)
N16925975: C12.2 U1.3(IN_D2N)
N16925996: C25.2 U1.12(IN_CLKN)
N16925999: C24.2 U1.11(IN_CLKP)
N16926002: C16.2 U1.9(IN_D0N)
N16926005: C15.2 U1.8(IN_D0P)
N16926008: C14.2 U1.6(IN_D1N)
N16926011: C13.2 U1.5(IN_D1P)
N16928798: J2.18(HPD) R33.2
N16928867: C7.2 R34.2
N16961958: U2.1(OE) U9.4(Y)
N16962991: L2.2 U6.5(L)
N16965307: R83.1 R120.1 U4.7(FSW)
N16965311: L1.1 U4.1(SW1) U4.2(SW2) U4.3(SW3)
N16965335: C34.1 U4.9(SS/TR)
N16968702: R98.2 U7.23(TEST0) U7.24(TEST1)
N16982334: R121.1 U8.7(WP)
N17009590: J18.1(CENTER) R123.1
N17009600: R123.2 U1.35(OUT_D2P) U10.6
N17009604: R124.2 U1.34(OUT_D2N) U10.7
N17009633: U1.28(OUT_D0N) U11.7
N17009635: U1.29(OUT_D0P) U11.6
N17009637: U1.31(OUT_D1N) U10.10
N17009639: U1.32(OUT_D1P) U10.9
N17009643: U1.26(OUT_CLKP) U11.9
N17009645: U1.25(OUT_CLKN) U11.10
N170364390: D2.1(A) R82.1

Pads without a net: D1 2; J2 20; J5 4 5 6 7 8 9; J13 4; R124 1; U7 2 13 14 15 16 17 19 20 21 22 31 32; U9 1

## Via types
v1: diameter 0.406, hole 0.203, TOP to BOTTOM, 302 vias
v2: diameter 0.61, hole 0.305, TOP to BOTTOM, 12 vias

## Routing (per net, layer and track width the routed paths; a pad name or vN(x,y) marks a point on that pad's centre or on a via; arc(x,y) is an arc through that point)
+1V8: length 5.3
  TOP w0.203: R92.1 18.69,72.81 18.72,72.78 R93.2 19.68,72.78 19.7,72.76 U7.4 v1(22.17,72.76)
  BOTTOM w0.203: C46.2 22.56,73.15 v1(22.17,72.76) 22.62,72.31 C47.2
GND: length 369.8
  TOP w0.203: U5.17 44.84,76.19 U5.21 ; v1(57.15,82.04) C32.2 v1(56.18,81.05) ; U4.16 53.05,75.6 52.55,75.1 ; U11.3 v1(75.28,40.13) ; U10.3 v1(75.28,43.18) ; U5.14 v1(44.84,78.74) ; U1.19 44.7,39.27 44.45,39.52 U1.49 ; U4.17 52.05,75.1 U4.6 ; U4.17 51.55,74.1 U4.8 ; U4.17 52.55,75.1 ; U10.8 v1(73.15,43.18) ; U1.49 42.06,41.91 41.81,41.66 U1.7 ; U1.49 46.84,41.91 47.09,41.66 U1.30 ; U1.49 45.2,42.66 U1.41 ; U11.8 v1(73.15,40.13) ; C50.2 v1(29.14,78.58) ; U4.15 52.55,75.1 ; C51.2 v1(24.66,78.56) ; U5.12 v1(46.14,78.71) ; U5.13 v1(45.49,78.74)
  TOP w0.356: P2.17 v1(79.8,36.41)
  TOP w0.381: v1(12.72,43.18) C1.2 v1(12.72,41.44) ; C34.2 v1(50.47,71.13) ; U6.1 v1(35.44,75.71) ; v1(35.49,76.76) U6.7 v1(37.39,76.76) ; v1(84.43,56.57) SW1.2 v1(84.43,52.52) ; U8.1 v1(13.76,63.22) ; U8.4 v1(13.79,59.41) ; v1(36.4,70.17) C57.2 v1(35.43,71.24) ; J2.8 v1(12.05,28.96) ; J2.19 12.35,34.46 12.33,34.49 12.23,34.49 12.18,34.54 v1(12.07,34.54) ; C35.2 v1(46.96,69.39) ; C35.2 v1(47.75,68.46) ; C35.2 v1(48.64,69.39) ; P2.2 v1(79.73,43.91) ; J2.2 v1(12.08,25.96) ; C30.2 v1(53.61,64.31) ; C30.2 v1(55.45,65.85) ; C30.2 v1(57.1,64.31) ; C30.2 v1(55.45,62.74) ; R93.1 v1(19.2,74.33) ; U7.8 v1(20.14,69.56) ; J2.11 v1(11.99,30.46) ; v1(34.21,78.34) C58.2 v1(33.29,79.38) ; J2.5 v1(12.04,27.46) ; U5.3 v1(45.49,72.26) ; C52.1 v1(17.01,67.36) ; P2.11 v1(79.81,39.41) ; U7.28 v1(25.67,77.48) ; C29.2 v1(73.33,55.48) ; J13.5 v1(18.85,78.72) ; C27.2 v1(79.04,64.95) ; U7.18 v1(28.34,70.36) ; J13.8 v1(17.55,81.23) ; R121.2 v1(22.1,63.53) ; v1(40.66,71.96) C36.2 v1(41.61,70.95) ; U2.3 v1(72.67,35.94) ; C28.2 v1(72.22,58.44) ; U5.2 v1(44.84,72.26) ; U8.2 v1(13.81,61.95) ; P2.8 v1(79.81,40.91) ; v1(84.43,63.04) SW1.1 v1(84.43,59.01) ; Y1.2 v1(26.33,82.55) ; J2.16 v1(14.96,32.96) ; C39.2 v1(11.99,77.09) ; C39.2 v1(13.03,77.95) ; C39.2 v1(13.03,76.23) ; C37.2 v1(48.34,78.99) ; P2.5 v1(79.76,42.41) ; v1(38.16,70.13) D2.2 v1(39.07,71.26) ; U3.2 v1(78.07,58.06) ; C31.2 v1(51.92,67.44) ; C31.2 v1(50.94,68.48) ; C31.2 v1(52.76,68.48) ; R30.1 v1(12.57,40.75) ; C38.2 v1(44.22,80.51) ; R91.1 v1(40.21,75.63) ; R101.2 v1(19.61,76.66) ; U9.3 v1(67.96,36.6) ; U5.4 v1(46.14,72.27) ; R120.2 v1(49.48,73.04) ; C59.1 v1(19.06,64.32) ; R115.2 v1(66.61,13.75) ; C26.2 v1(75.36,53.16) ; Y1.4 v1(29.59,79.95) ; U8.3 v1(13.78,60.68)
  L2 w0.508: J9.2 67.97,74.92 ; J9.2 70.05,72.83 ; J9.2 67.97,70.75 ; J9.2 65.89,72.83 ; J13.7 15.93,79.42 ; J13.7 15.33,80.12 ; J13.7 15.33,78.72 ; J13.7 14.72,79.42 ; 22.4,82.42 J13.9 21.73,81.29 ; 77.52,32.66 P2.20 ; P2.20 79.4,33.64 ; P2.20 79.4,31.68 ; P2.20 81.28,32.66 ; 3.59,43.89 P1.23 ; P1.23 4.92,44.82 ; P1.23 3.59,45.75 ; P1.23 2.26,44.82 ; 19.78,78.72 J13.6 ; J13.6 19.17,79.42 ; J13.6 20.38,79.42 ; J13.6 19.78,80.12 ; P2.22 85.36,48.09 ; P2.22 84.03,47.16 ; P2.22 85.36,46.23 ; P2.22 86.69,47.16 ; P1.20 11.43,44.82 ; P1.20 9.55,45.8 ; P1.20 7.68,44.82 ; P1.20 9.55,43.84 ; P1.22 3.59,60.25 ; P1.22 2.26,59.32 ; P1.22 3.59,58.39 ; P1.22 4.92,59.32 ; 66.1,47.63 J18.4 ; J18.4 67.33,48.86 ; J18.4 68.56,47.63 ; J18.4 67.33,46.4 ; 72.41,46.4 J18.5 ; J18.5 73.64,47.63 ; J18.5 71.18,47.63 ; J18.5 72.41,48.86 ; R76.3 66.15,4.84 ; R76.3 65.17,5.82 ; R76.3 65.17,3.86 ; R76.3 64.2,4.84 ; 61.27,53.65 LP8.1 ; LP8.1 61.27,56.09 ; LP8.1 62.49,54.87 ; LP8.1 60.05,54.87 ; 17.84,2.74 J5.10 ; J5.10 18.91,3.81 ; J5.10 16.78,3.81 ; J5.10 17.84,4.88 ; 67.33,51.48 J18.3 ; J18.3 67.33,53.94 ; J18.3 68.56,52.71 ; J18.3 66.1,52.71 ; LP9.1 44.61,11.2 ; LP9.1 42.17,11.2 ; LP9.1 43.39,9.98 ; LP9.1 43.39,12.42 ; 7.68,59.32 P1.21 ; P1.21 9.55,58.34 ; P1.21 11.43,59.32 ; P1.21 9.55,60.3 ; 72.77,74 J9.3 ; J9.3 74.85,76.09 ; J9.3 70.69,76.09 ; J9.3 72.77,78.17 ; 71.18,52.71 J18.2 ; J18.2 73.64,52.71 ; J18.2 72.41,51.48 ; J18.2 72.41,53.94 ; P2.23 86.69,32.66 ; P2.23 85.36,31.73 ; P2.23 84.03,32.66 ; P2.23 85.36,33.59 ; 13.38,81.29 J13.10 12.7,82.42 ; 79.4,46.18 P2.21 ; P2.21 77.52,47.16 ; P2.21 79.4,48.14 ; P2.21 81.28,47.16 ; 35.69,63.63 LP7.1 ; LP7.1 36.91,64.85 ; LP7.1 35.69,66.07 ; LP7.1 34.47,64.85 ; 26.94,3.81 J5.2 ; J5.2 29.07,3.81 ; J5.2 28,2.74 ; J5.2 28,4.88
  L5 w0.508: 61.27,53.65 LP8.1 ; LP8.1 62.49,54.87 ; LP8.1 61.27,56.09 ; LP8.1 60.05,54.87 ; 42.17,11.2 LP9.1 ; LP9.1 44.61,11.2 ; LP9.1 43.39,9.98 ; LP9.1 43.39,12.42 ; 34.47,64.85 LP7.1 ; LP7.1 35.69,63.63 ; LP7.1 36.91,64.85 ; LP7.1 35.69,66.07 ; 16.78,3.81 J5.10 ; J5.10 17.84,2.74 ; J5.10 17.84,4.88 ; J5.10 18.91,3.81 ; P2.21 79.4,48.14 ; P2.21 79.4,46.18 ; P2.21 81.28,47.16 ; P2.21 77.52,47.16 ; 67.33,46.4 J18.4 ; J18.4 67.33,48.86 ; J18.4 66.1,47.63 ; J18.4 68.56,47.63 ; 15.33,78.72 J13.7 ; J13.7 15.33,80.12 ; J13.7 15.93,79.42 ; J13.7 14.72,79.42 ; 2.26,59.32 P1.22 ; P1.22 3.59,60.25 ; P1.22 4.92,59.32 ; P1.22 3.59,58.39 ; P2.20 81.28,32.66 ; P2.20 77.52,32.66 ; P2.20 79.4,31.68 ; P2.20 79.4,33.64 ; 71.18,52.71 J18.2 ; J18.2 73.64,52.71 ; J18.2 72.41,51.48 ; J18.2 72.41,53.94 ; P1.23 4.92,44.82 ; P1.23 2.26,44.82 ; P1.23 3.59,43.89 ; P1.23 3.59,45.75 ; P2.22 85.36,48.09 ; P2.22 85.36,46.23 ; P2.22 84.03,47.16 ; P2.22 86.69,47.16 ; J9.3 74.85,76.09 ; J9.3 70.69,76.09 ; J9.3 72.77,74 ; J9.3 72.77,78.17 ; 13.38,81.29 J13.10 12.7,82.42 ; 26.94,3.81 J5.2 ; J5.2 29.07,3.81 ; J5.2 28,4.88 ; J5.2 28,2.74 ; J18.3 67.33,53.94 ; J18.3 66.1,52.71 ; J18.3 68.56,52.71 ; J18.3 67.33,51.48 ; 9.55,43.84 P1.20 ; P1.20 7.68,44.82 ; P1.20 9.55,45.8 ; P1.20 11.43,44.82 ; J18.5 72.41,48.86 ; J18.5 71.18,47.63 ; J18.5 72.41,46.4 ; J18.5 73.64,47.63 ; P1.21 11.43,59.32 ; P1.21 9.55,60.3 ; P1.21 9.55,58.34 ; P1.21 7.68,59.32 ; 19.17,79.42 J13.6 ; J13.6 20.38,79.42 ; J13.6 19.78,78.72 ; J13.6 19.78,80.12 ; J9.2 67.97,74.92 ; J9.2 67.97,70.75 ; J9.2 70.05,72.83 ; J9.2 65.89,72.83 ; P2.23 85.36,33.59 ; P2.23 85.36,31.73 ; P2.23 86.69,32.66 ; P2.23 84.03,32.66 ; 65.17,3.86 R76.3 ; R76.3 66.15,4.84 ; R76.3 65.17,5.82 ; R76.3 64.2,4.84 ; 22.4,82.42 J13.9 21.73,81.29
  BOTTOM w0.203: R36.1 v1(28.99,28.56) ; v1(22.27,73.9) 21.96,73.58 C42.1 ; D1.1 v1(13.83,15.83) ; Q2.2 v1(11.98,17.84) ; R86.1 v1(50.99,76.17) ; R35.1 v1(22.68,28.54) ; Q1.2 v1(11.1,20.73)
  BOTTOM w0.305: 46.37,40.06 47.01,39.42 C17.2 ; 46.37,40.06 46.37,39.19 C19.2 ; 46.37,40.06 v2(45.96,40.47) ; R125.2 v1(42.72,49.5) ; C23.2 v1(48.5,47.45) ; R126.2 v1(42.18,49.5)
  BOTTOM w0.356: C22.2 42.13,39.69 v2(42.91,40.47) 42.91,39.06 C21.2 ; v2(42.91,43.52) 42.91,45.1 43.15,45.34 C10.2
  BOTTOM w0.381: P1.8 v1(9.13,53.07) ; R69.2 v1(59.43,22.78) ; P1.5 v1(9.17,54.57) ; R73.2 v1(41.08,1.87) ; v1(44.81,51.07) C8.2 ; C9.2 v1(39.91,38.02) ; C49.1 v1(24.39,70.36) ; C46.1 v1(24.24,73.15) ; R67.2 v1(61.52,13.23) ; C40.1 v1(27.46,73.44) ; R75.1 v1(66.58,20.27) ; R64.2 v1(58.34,1.95) ; P1.17 v1(9.16,48.57) ; C20.2 v1(50.59,38.14) ; R70.2 v1(52.69,14.98) ; C47.1 v1(24.28,72.31) ; P1.2 v1(9.17,56.07) ; R60.2 v1(44.33,15.11) ; C18.2 v1(41.04,46) ; R12.1 v1(14.93,20.58) ; R74.2 v1(80.06,17.08) ; P1.11 v1(9.14,51.57) ; C41.1 v1(28.27,73.35) ; C45.2 v1(24.36,71.17) ; R62.2 v1(50.22,1.78)
  vias: v1(21.64,44.86) v1(21.64,40.94) v1(21.62,38.79) v1(21.67,46.99) v1(21.67,43.97) v1(21.67,41.83) v1(21.67,37.87) v1(21.69,35.74) v1(44.38,76.65) v1(44.38,75.89) v1(44.38,75.13) v1(44.38,74.37) v1(45.14,76.65) v1(45.14,74.37) v1(45.9,76.65) v1(45.9,74.37) v1(46.67,76.65) v1(46.67,75.89) v1(46.67,75.13) v1(46.67,74.37) v1(51.81,75.4) v1(51.81,74.89) v1(51.81,74.38) v1(52.32,75.4) v1(52.32,74.38) v1(52.83,75.4) v1(52.83,74.89) v1(52.83,74.38) v2(42.91,42.5) v2(42.91,41.49) v2(43.67,43.52) v2(43.67,40.47) v2(45.19,43.52) v2(45.19,40.47) v2(45.96,43.52) v2(45.96,42.5) v2(45.96,41.49)
VCC_3P3V: length 22.8
  TOP w0.203: U3.5 v1(75.26,58.06) ; U3.6 v1(75.31,57.11) ; U1.13 v1(41.7,37.41) ; U1.43 v1(44.2,46.41)
  TOP w0.381: R78.1 v1(77.22,54.13) ; R84.1 v1(50.97,79.75) ; C29.1 v1(73.33,57.57)
  TOP w0.508: LP5.1 50.83,81.79 ; LP5.1 49.61,80.57 ; LP5.1 48.39,81.79 ; LP5.1 49.61,83.01
  L4 w0.508: 48.39,81.79 LP5.1 ; LP5.1 49.61,83.01 ; LP5.1 49.61,80.57 ; LP5.1 50.83,81.79
  BOTTOM w0.203: C9.1 41.45,37.66 v1(41.7,37.41) ; R59.1 21.82,14.53 v1(21.82,14.32)
  BOTTOM w0.381: R61.1 v1(50,6.88) ; R58.1 v1(34.77,14.42) ; C10.1 44.2,45.88 v1(44.2,46.41) 44.2,46.67 44.81,47.29 C8.1 ; R66.1 v1(59.37,27.88) ; R68.1 v1(52.47,20.09) ; R71.1 v1(36.34,6.94) ; R63.1 v1(58.11,6.97) ; R57.1 v1(44.35,20.18) ; R65.1 v1(61.48,18.33) ; R72.1 v1(75.66,22.06)
  vias: v1(47.47,82.56) v1(47.47,82.05) v1(47.47,81.54) v1(47.98,82.56) v1(47.98,82.05) v1(47.98,81.54)
VDD_1P1V: length 21.6
  TOP w0.203: U1.14 42.2,37.47 v1(42.26,37.41) ; U1.24 47.2,37.97 v1(47.66,37.51) ; U1.23 v1(46.71,37.45)
  TOP w0.381: U1.37 47.2,45.53 47.21,46.41 v1(47.22,46.42) ; U1.48 41.4,45.23 v1(40.93,45.23) ; R89.1 v1(43.08,70.73)
  TOP w0.508: 42.98,67.46 LP6.1 ; LP6.1 42.98,69.9 ; LP6.1 44.2,68.68 ; LP6.1 41.76,68.68
  L3 w0.508: 42.98,67.46 LP6.1 ; LP6.1 41.76,68.68 ; LP6.1 42.98,69.9 ; LP6.1 44.2,68.68
  BOTTOM w0.381: C21.1 42.95,37.79 42.56,37.41 v1(42.26,37.41) 42.26,37.96 C22.1 ; C17.1 47.07,38.03 47.45,37.65 47.52,37.65 v1(47.66,37.51) 47.66,38.33 C20.1 ; C19.1 46.25,37.9 v1(46.71,37.45) ; v1(40.93,45.23) 41.29,45.23 C18.1 ; C23.1 47.23,46.41 v1(47.22,46.42)
  vias: v1(44.18,70.51) v1(44.18,70) v1(44.18,69.49) v1(44.68,70.51) v1(44.68,70) v1(44.68,69.49)
ARC_OUT: length 36.2
  TOP w0.203: C6.1 24.97,30.87 24.97,29.28 R114.1 24.46,27.69 24.02,27.25 LP3.1
  BOTTOM w0.203: P1.14 14.05,50.07 16.92,47.2 16.92,37.77 19.05,35.63 19.05,29.86 21.89,27.02 LP3.1
AUX_SRCN/ARC_OUT: length 47.8
  TOP w0.127: C2.1 v1(24.83,25.24) ; v1(43.72,46.88) 43.59,46.75 43.59,45.65 U1.44 ; R114.2 25.58,28.85 25.58,29.69 v1(25.59,29.7)
  BOTTOM w0.127: v1(43.72,46.88) 43.72,47.27 43.59,47.4 43.59,49.84 42.26,51.17 38.2,51.17 25.75,38.73 25.75,36.61 25.54,36.4 24.87,36.4 24.69,36.23 24.69,35.99 24.87,35.82 25.54,35.82 25.75,35.61 25.75,35.44 25.54,35.23 24.84,35.23 24.67,35.06 24.67,34.82 24.84,34.65 25.54,34.65 25.75,34.44 25.75,34.03 LP1.1 24.98,32.45 C4.1 25.59,30.29 v1(25.59,29.7) 25.59,29.24 25.71,29.11 25.71,26.12 v1(24.83,25.24)
AUX_SRCP/SPDIF_IN: length 47.8
  TOP w0.127: R113.2 26.11,28.84 26.11,29.69 v1(26.12,29.7) ; v1(26.36,25.83) 26.81,25.37 v1(26.81,23.13) ; v1(43.18,46.88) 43.31,46.75 43.31,45.64 U1.45 ; C3.1 v1(24.84,22.52)
  BOTTOM w0.127: v1(26.36,25.83) 25.99,26.19 25.99,29.11 26.12,29.24 v1(26.12,29.7) 26.12,30.25 C5.1 26.74,32.42 LP2.1 26.03,34.01 26.03,38.61 38.31,50.89 42.14,50.89 43.31,49.73 43.31,47.4 43.18,47.27 v1(43.18,46.88) ; v1(24.84,22.52) 26.2,22.52 v1(26.81,23.13)
BOARD_3P3V: length 26.6
  TOP w0.203: U7.25 v1(28.07,75.48) ; R29.2 23.32,22.39 v1(22.92,22.39) ; R87.1 v1(50.57,78.82) ; R81.1 v1(51.41,78.87) ; v1(22.89,25.31) 23.37,25.31 R28.2 ; U8.8 v1(20.04,63.77) ; R99.1 v1(23.29,65.17) ; R102.1 v1(24.84,65.28)
  TOP w0.279: U4.14 v1(54.5,74.6)
  TOP w0.381: L2.1 v1(37.89,81.69) ; L2.1 v1(36.47,82.64) ; L2.1 v1(36.47,80.78) ; R100.1 v1(22.3,58.97) ; C35.1 v1(46.86,71.68) ; C35.1 v1(48.65,71.68) ; C35.1 v1(47.75,72.8) ; R88.1 v1(48.26,79.83) ; U7.3 v1(20.07,73.56) ; R92.2 v1(18.21,74.35) ; R56.2 v1(69.88,36.03) ; U5.7 v1(48.64,74.89) ; U6.4 v1(37.66,77.81) ; U5.6 v1(48.68,74.24) ; R79.1 v1(79.93,64.9) ; U5.8 v1(48.64,75.54) ; R103.1 v1(17.92,68.78) ; U9.5 v1(69.56,37.91) ; U5.5 v1(47.21,73.14) ; C59.2 v1(20.1,64.27) ; U6.6 v1(35.29,77.81) ; v1(33.19,81.66) C58.1 v1(34.21,82.72) ; R98.1 v1(32.02,73.93) ; U5.10 v1(47.89,77.29)
  BOTTOM w0.203: C40.2 27.85,75.48 v1(28.07,75.48) 28.27,75.29 C41.2 ; C42.2 20.62,73.56 v1(20.07,73.56) ; R85.2 v1(49.78,77.99) ; R27.2 v1(11.33,29.98)
  vias: v1(52.18,82.71) v1(52.18,82.2) v1(52.18,81.7) v1(52.18,81.19) v1(52.69,82.71) v1(52.69,82.2) v1(52.69,81.7) v1(52.69,81.19)
BOARD_5V: length 7.7
  TOP w0.356: P2.18 79.58,35.91 79.59,35.9 80.25,35.9 v1(80.32,35.83)
  TOP w0.381: R82.2 v1(38.63,75.76) ; U2.5 v1(74.27,38.06)
  BOTTOM w0.203: R16.2 v1(20.96,22.51) ; v1(21.06,25.5) 21.32,25.23 R17.2
  BOTTOM w0.356: R104.1 v1(13.7,47.03)
  BOTTOM w0.381: v1(75.46,38.23) 75.73,38.51 R45.2 ; R10.2 v1(16.44,12.92) ; R11.2 v1(8.18,18.9) ; R46.2 v1(75.92,35.31)
  vias: v1(36.19,74.82) v1(36.95,74.82)
BOARD_IN: length 5.7
  TOP w0.508: SW2.2 62.79,70.74 ; SW2.2 61.37,72.16 ; SW2.2 59.94,70.74 ; SW2.2 61.37,69.32
C_DPRX_LN0N: length 21.1
  TOP w0.127: R106.2 22.09,45.78 21.6,45.78 17,41.19 17,31.5 15.83,30.32 15.29,30.32 14.93,29.96 J2.10
C_DPRX_LN0P: length 21.1
  TOP w0.127: J2.12 14.93,30.96 15.29,30.6 15.71,30.6 16.73,31.61 16.73,41.3 21.49,46.06 22.09,46.06 R105.2
C_DPRX_LN1N: length 21.1
  TOP w0.127: J2.7 14.93,28.46 15.29,28.82 17.47,28.82 18.25,29.6 18.25,40.37 20.64,42.76 22.09,42.76 R110.2
C_DPRX_LN1P: length 21.1
  TOP w0.127: R107.2 22.09,43.04 20.52,43.04 17.97,40.49 17.97,29.72 17.36,29.1 15.29,29.1 14.93,29.46 J2.9
C_DPRX_LN2N: length 21.1
  TOP w0.127: J2.4 14.93,26.96 15.29,27.32 18.79,27.32 19.6,28.13 19.6,31.98 20.33,32.71 20.33,33.58 19.6,34.31 19.6,38.99 20.32,39.71 22.06,39.71 R111.2
C_DPRX_LN2P: length 21.1
  TOP w0.127: R108.2 22.06,39.99 20.21,39.99 19.32,39.1 19.32,34.19 20.05,33.46 20.05,32.83 19.32,32.1 19.32,28.25 18.67,27.6 15.29,27.6 14.93,27.96 J2.6
C_DPRX_LN3N: length 21.1
  TOP w0.127: R112.2 22.12,36.66 21.31,36.66 20.87,36.22 20.87,35.06 21.88,34.04 21.88,32.39 20.77,31.27 20.77,30.18 21.89,29.05 21.89,28.19 19.53,25.82 18.63,25.82 18.07,26.38 16.62,26.38 16.06,25.82 15.26,25.82 14.9,25.46 J2.1
C_DPRX_LN3P: length 21.1
  TOP w0.127: J2.3 14.92,26.46 15.28,26.1 15.95,26.1 16.5,26.66 18.18,26.66 18.74,26.1 19.41,26.1 21.61,28.3 21.61,28.94 20.49,30.06 20.49,31.39 21.6,32.5 21.6,33.93 20.59,34.94 20.59,36.34 21.19,36.94 22.12,36.94 R109.2
CEC_EN: length 27.7
  TOP w0.203: v1(48.55,33.9) 52.03,33.9 55.82,37.69 U9.2 ; U1.18 v1(44.2,37.3)
  BOTTOM w0.203: v1(44.2,37.3) 47.61,33.9 v1(48.55,33.9)
CEC_SRC: length 147.9
  TOP w0.203: J2.14 15.45,31.96 15.67,32.18 15.67,56.33 16.82,57.48 29.69,57.48 31.44,59.23 70.68,59.23 77.36,65.91 81.18,65.91 82.63,64.46 82.63,36.95 79.84,34.16 77.46,34.16 74.51,31.2 70.39,31.2 69.79,31.8 J16.1 69.79,34.42 R56.1 71.4,36.87 71.56,37.03 U2.2
DP_CAD: length 2.2
  TOP w0.203: J2.13 v1(12.08,31.46)
  BOTTOM w0.203: R27.1 11.92,31.46 v1(12.08,31.46)
DP_SCL_SRC: length 35.3
  TOP w0.127: v1(22.85,23) 22.85,23.4 22.99,23.54 23.43,23.54 R29.1 C3.2 24.42,23.75 25.1,23.75 25.63,23.22 25.63,22.2 24.97,21.54 16.65,21.54 13.61,24.58 10.99,24.58 9.89,25.67 9.89,29.78 10.04,29.93 10.4,29.93 10.55,30.07 10.55,30.29 10.4,30.43 10.04,30.43 9.89,30.58 9.89,30.79 10.04,30.94 10.36,30.94 10.51,31.09 10.51,31.3 10.36,31.45 10.04,31.45 9.89,31.6 9.89,32.22 10.5,32.82 11.83,32.82 12.19,32.46 J2.15
  BOTTOM w0.127: R31.2 v1(22.85,23)
DP_SDA_SRC: length 35.3
  TOP w0.127: J2.17 12.19,33.46 11.83,33.1 10.38,33.1 9.61,32.33 9.61,25.56 10.87,24.3 13.49,24.3 16.54,21.26 25.09,21.26 25.91,22.09 25.91,23.33 25.22,24.03 24.4,24.03 C2.2 R28.1 23.44,24.19 23,24.19 22.85,24.34 v1(22.85,24.75)
  BOTTOM w0.127: R32.2 v1(22.85,24.75)
DPRX_GND: length 34.2
  TOP w0.508: J2.21 10.97,39.22 R30.2 10.97,42.23 C1.1
  L2 w1.016: J2.21 J2.22 4.18,34.16 5.3,33.04 5.3,29.66 4.09,28.45 4.09,24.07 4.18,23.97 J2.23 J2.24
EN1P2: length 1.9
  TOP w0.203: R88.2 C37.1 46.79,78.99 U5.11
EQ_SEL_A0: length 21.3
  TOP w0.203: J12.2 48.51,21.23 48.51,27.74 45.7,30.55 U1.21
EQ_SEL_HI: length 1.8
  BOTTOM w0.203: J12.1 51.95,21.62 51.98,21.65 R68.2
EQ_SEL_LO: length 2
  BOTTOM w0.203: R70.1 51.64,16.54 51.63,16.54 J12.3
FB_3PT3V: length 2
  TOP w0.203: U4.5 v1(50.23,75.6)
  BOTTOM w0.203: R85.1 50.37,76.19 R86.2 50.23,76.05 v1(50.23,75.6)
HDMI_CEC_SNK: length 8.2
  TOP w0.203: P2.13 76.85,38.41 74.82,36.38 U2.4 74.27,36 74.87,35.39 J16.3
HDMI_CEC_SRC: length 100.8
  BOTTOM w0.203: J16.2 73.01,32.75 73.02,32.75 73.58,32.18 75.69,32.18 78.06,34.55 78.06,45.12 65.88,57.29 8.93,57.29 8.36,56.73 8.36,51.08 8.87,50.57 P1.13
HDMI_IN_5V: length 2.5
  BOTTOM w0.356: P1.18 R104.2
HDMI_SCL_SRC: length 39.7
  BOTTOM w0.127: R24.2 21.89,23.61 R16.1 21.66,23.73 20.13,23.73 16.19,27.67 16.19,34.49 14.65,36.03 9.76,36.03 7.08,38.72 7.08,48.46 8.08,49.46 10.43,49.46 P1.15
HDMI_SDA_SRC: length 39.7
  BOTTOM w0.127: P1.16 10.43,49.18 8.19,49.18 7.36,48.34 7.36,38.84 9.88,36.31 14.77,36.31 16.47,34.61 16.47,27.79 18.69,25.57 18.9,25.57 19,25.67 19.21,25.67 19.35,25.52 19.35,25.31 19.26,25.21 19.26,25 19.41,24.85 19.62,24.85 19.68,24.91 19.89,24.91 20.04,24.76 20.04,24.55 19.98,24.49 19.98,24.28 20.25,24.01 21.66,24.01 R17.1 21.88,24.15 R25.2
HDMI_SEL#_TEST_A1: length 23.3
  TOP w0.203: U1.27 v1(48.93,40.16)
  BOTTOM w0.203: v1(48.93,40.16) 53.44,40.16 63.18,30.43 63.18,28.62 J7.2
HPD_SNK: length 34.1
  TOP w0.203: P2.19 v1(77.05,35.41) ; U1.33 v1(49.08,43.16)
  BOTTOM w0.203: v1(77.05,35.41) 76.41,34.77 68.91,34.77 60.52,43.16 v1(49.08,43.16)
HPD_SRC: length 61.4
  TOP w0.203: U1.4 v1(39.84,43.16)
  BOTTOM w0.203: v1(39.84,43.16) 35.72,39.04 35.72,34.69 37.5,32.9 37.5,30.42 35.27,28.19 32.9,28.19 31.92,27.22 31.92,23.23 29.1,20.41 22.4,20.41 21.59,19.6 J1.1 17.01,19.6 16.98,19.56 R5.1 16.19,20.04 16.17,20.06 16.17,20.18 10.28,26.06 10.28,33.37 R33.1
HPD_SRC_CONN: length 5.8
  BOTTOM w0.203: R10.1 17.94,14.56 J1.3 ; R10.1 16.46,14.55 16,14.55 14.74,13.29 R13.2 ; R10.1 16.47,15.39 D1.3
HPD_SRC_HDMI_RX_CONN: length 48.3
  TOP w0.203: J1.2 16.47,17.06 13.57,19.96 3.88,19.96 1.78,22.05 1.78,40.28 v1(9.07,47.57)
  BOTTOM w0.203: P1.19 v1(9.07,47.57)
I2C_EN_HI: length 2
  BOTTOM w0.203: J3.1 43.85,21.7 43.86,21.7 R57.2
I2C_EN_LO: length 2
  BOTTOM w0.203: R60.1 43.84,16.6 43.82,16.62 J3.3
I2C_EN_PIN: length 24.7
  TOP w0.203: U1.10 v1(39.95,40.16)
  BOTTOM w0.203: J3.2 40.81,20.72 40.81,23.52 42.26,24.97 42.26,34.97 39.95,37.28 39.25,37.98 39.25,39.46 v1(39.95,40.16)
IN_CLKN: length 0.9
  TOP w0.203: C25.1 23.9,36.42 R112.1
IN_CLKP: length 0.9
  TOP w0.203: C24.1 23.9,37.19 R22.1
IN_D0N: length 0.9
  TOP w0.203: C16.1 22.98,39.47 R111.1
IN_D0P: length 0.9
  TOP w0.203: C15.1 23.84,40.23 R20.1
IN_D1N: length 0.9
  TOP w0.203: C14.1 23.01,42.51 R110.1
IN_D1P: length 0.9
  TOP w0.203: R107.1 23.84,43.28 C13.1
IN_D2N: length 0.9
  TOP w0.203: C12.1 23.83,45.54 R15.1
IN_D2P: length 0.9
  TOP w0.203: R14.1 23.83,46.3 C11.1
OE: length 38.3
  TOP w0.203: U1.42 44.7,46.4 45.93,47.63 46.58,47.63 48.1,49.14 48.1,51 53.53,56.44 69.25,56.44 70.83,54.85 74.88,54.85 74.88,54.85 C26.1 75.37,54.86 R77.1
OUT_CLKN: length 4
  TOP w0.127: P2.12 77.08,38.91 76.74,39.25 74.72,39.25 U11.1
OUT_CLKP: length 4
  TOP w0.127: U11.2 74.7,39.53 76.74,39.53 77.12,39.91 P2.10
OUT_D0N: length 4
  TOP w0.127: P2.9 77.06,40.41 76.73,40.74 74.71,40.74 U11.4
OUT_D0P: length 4
  TOP w0.127: P2.7 77.12,41.41 76.73,41.02 74.71,41.02 U11.5
OUT_D1N: length 4
  TOP w0.127: P2.6 77.15,41.91 76.78,42.28 74.7,42.28 U10.1
OUT_D1P: length 4
  TOP w0.127: U10.2 74.72,42.56 76.79,42.56 77.15,42.91 P2.4
OUT_D2N: length 4
  TOP w0.127: U10.4 74.7,43.78 76.75,43.78 77.12,43.41 P2.3
OUT_D2P: length 4
  TOP w0.127: P2.1 77.12,44.41 76.77,44.06 74.72,44.06 U10.5
PB_MANUAL_RESET: length 14
  TOP w0.203: U3.3 77.22,59.59 77.9,60.27 77.9,60.52 77.88,60.54 R80.1 SW1.3 ; 79.91,63.31 R79.2 ; 79.91,63.31 SW1.3 ; 79.91,63.31 C27.1 ; SW1.3 SW1.4
PRE_SEL: length 36.8
  TOP w0.203: U1.20 45.2,17.02 J15.2
PRE_SEL_HI: length 2
  BOTTOM w0.203: J15.1 57.11,8.61 57.13,8.59 R63.2
PRE_SEL_LO: length 2.2
  BOTTOM w0.203: R64.1 57.85,3.54 57.85,3.53 J15.3
PWRIN_SW: length 15
  TOP w0.508: J9.1 75.11,69.84 ; J9.1 70.43,69.84 ; J9.1 72.77,67.5 ; J9.1 72.77,72.17 ; 59.94,66.04 SW2.1 ; SW2.1 61.37,64.62 ; SW2.1 61.37,67.46 ; SW2.1 62.79,66.04
REG_PG: length 0.7
  TOP w0.381: R80.2 v1(77.2,62.06)
  vias: v1(49.43,77.36) v1(49.43,76.8)
RSTIN: length 4.7
  TOP w0.203: U7.9 21.98,68.24 21.1,67.36 C52.2 19.53,68.14 19.52,68.15 R103.2
SCL_CTL: length 39.8
  TOP w0.203: U1.15 42.7,34.47 35.91,27.68 35.91,27.31 35.48,26.87 33.05,26.87 32.7,26.53 32.7,25.75 33.05,25.4 35.48,25.4 35.91,24.97 35.91,24.36 35.48,23.93 33.05,23.93 32.73,23.6 32.73,22.78 33.05,22.45 35.48,22.45 35.91,22.02 35.91,19.44 J4.2
  BOTTOM w0.203: J4.2 34.28,16.01 34.29,16.02 R58.2
SCL_CTL_USB: length 103.7
  TOP w0.203: U7.30 v1(24.07,77.47)
  BOTTOM w0.203: J4.1 25.8,11.88 10.93,11.88 8.82,13.99 8.82,15.52 5.68,18.67 5.68,63.55 17.73,75.6 22.89,75.6 24.07,76.79 v1(24.07,77.47)
SCL_SNK: length 40.2
  TOP w0.127: P2.15 77.48,37.41 77.37,37.3 76.76,37.3 v1(76.63,37.43) ; U1.38 46.6,45.63 46.6,46.76 v1(46.72,46.88)
  BOTTOM w0.127: v1(76.63,37.43) 76.55,37.51 75.96,37.51 R45.1 75.47,37.47 75.28,37.28 73.34,37.28 72.95,37.66 72.95,38.04 72.78,38.21 72.41,38.21 72.24,38.38 72.24,38.75 72.06,38.93 71.69,38.93 65.01,45.6 47,45.6 46.6,46 46.6,46.37 46.72,46.48 v1(46.72,46.88) 46.59,47 46.59,48.35 R127.1
SCL_SRC: length 43.1
  TOP w0.127: v1(40.69,46.57) 40.8,46.69 41.22,46.69 41.62,47.08 41.62,47.91 42.1,48.39 46.11,48.39 46.58,48.86 46.58,49.42 v1(46.73,49.58)
  BOTTOM w0.127: R129.2 v1(40.69,46.57) 40.58,46.68 40.23,46.68 30.97,37.42 30.97,25.17 29.54,23.74 23.52,23.74 R24.1 ; R127.2 v1(46.73,49.58)
SDA_CTL: length 39.7
  TOP w0.203: U1.16 43.2,34.02 37.05,27.87 37.05,18.47 33.29,14.71 26.55,14.71 25.25,16 J6.2
  BOTTOM w0.203: R59.2 22.72,16.02 22.75,16 J6.2
SDA_CTL_USB: length 95.5
  TOP w0.203: U7.29 v1(24.87,77.43)
  BOTTOM w0.203: v1(24.87,77.43) 24.87,76.64 23.16,74.93 17.76,74.93 6.3,63.47 6.3,18.68 9.27,15.71 9.27,14.25 11.19,12.33 18.33,12.33 20.32,14.32 20.32,16.84 22.01,18.54 J6.1
SDA_SNK: length 40.2
  TOP w0.127: U1.39 46.2,45.6 46.32,45.72 46.32,46.74 v1(46.18,46.88) ; v1(76.63,36.89) 76.76,37.02 77.38,37.02 77.48,36.91 P2.16
  BOTTOM w0.127: R128.1 46.31,48.36 46.31,47 v1(46.18,46.88) 46.18,46.48 46.32,46.34 46.32,45.88 46.88,45.32 64.9,45.32 73.22,37 75.28,37 75.44,36.83 R46.1 76.58,36.83 v1(76.63,36.89)
SDA_SRC: length 43.1
  TOP w0.127: v1(40.69,47.11) 40.83,46.97 41.11,46.97 41.34,47.2 41.34,48.03 41.98,48.67 45.99,48.67 46.3,48.98 46.3,49.46 v1(46.18,49.58)
  BOTTOM w0.127: R32.1 23.52,24.02 23.98,24.02 24.13,24.17 24.13,24.27 24.27,24.42 24.48,24.42 24.63,24.27 24.63,24.17 24.78,24.02 29.42,24.02 30.69,25.28 30.69,37.53 40.11,46.96 40.54,46.96 v1(40.69,47.11) R130.2 ; R128.2 v1(46.18,49.58)
SIG_EN: length 34.4
  TOP w0.203: J11.2 40.44,7.65 40.44,29.83 43.7,33.1 U1.17
SIG_EN_HI: length 2.4
  BOTTOM w0.203: J11.1 37.77,8.5 37.74,8.53 R71.2
SIG_EN_LO: length 2.3
  BOTTOM w0.203: R73.1 39.72,3.41 39.71,3.42 J11.3
SLEW_CTL: length 37.7
  TOP w0.203: U1.40 v1(45.7,46.51)
  BOTTOM w0.203: v1(45.7,46.51) 44.38,45.19 44.38,38.5 43.5,37.62 43.5,33.31 J10.2
SLEW_CTL_HI: length 2
  BOTTOM w0.203: R65.2 60.46,19.85 J10.1
SLEW_CTL_LO: length 2
  BOTTOM w0.203: R67.1 61.03,14.72 60.98,14.77 J10.3
SPDIF_IN: length 142.3
  TOP w0.203: R34.1 27.52,29.06 R113.1 27.23,27.72 27.74,27.21 LP4.1 26.43,27.04 25.14,25.75 22.63,25.75 v1(22.05,26.32) ; P2.14 81.15,37.91 82.03,38.79 82.03,64.27 80.92,65.38 77.66,65.38 70.83,58.55 31.62,58.55 29.94,56.87 16.95,56.87 16.22,56.14 v1(16.22,43.15)
  BOTTOM w0.203: v1(16.22,43.15) 16.22,36.75 17.86,35.1 17.86,28.57 20.12,26.32 v1(22.05,26.32)
SS1P2: length 1
  TOP w0.203: C38.1 44.19,78.88 U5.15
SWAP/POL: length 47.9
  TOP w0.203: U1.1 v1(39.9,44.66)
  BOTTOM w0.203: v1(39.9,44.66) 40.7,43.86 40.7,42.06 36.36,37.72 36.36,35.02 39.59,31.79 39.59,11.96 45.66,5.9 J17.2
SWAP_POL_HI: length 2.1
  BOTTOM w0.203: J17.1 48.85,8.44 48.86,8.45 R61.2
SWAP_POL_LO: length 2.3
  BOTTOM w0.203: R62.1 48.87,3.34 48.85,3.36 J17.3
TPS3808_CT: length 1.3
  TOP w0.203: U3.4 73.76,59.01 73.75,59 C28.1
TX_TERM_CTL: length 43.2
  TOP w0.203: U1.36 v1(49.03,44.66)
  BOTTOM w0.203: v1(49.03,44.66) 48.41,44.04 48.41,42.98 50.3,41.08 57.65,41.08 66.62,32.11 66.62,28.9 74.36,21.16 76.81,21.16 76.82,21.17 J14.2
TX_TERM_CTL_HI: length 2.1
  BOTTOM w0.203: R72.2 76.82,23.71 76.82,23.71 J14.1
TX_TERM_CTL_LO: length 2.3
  BOTTOM w0.203: R74.1 79.35,18.63 J14.3
USB_5V: length 7.8
  TOP w0.381: v1(16.25,80.77) J13.1 v1(16.25,78.68)
  BOTTOM w0.508: SW2.3 61.37,76.86 ; SW2.3 62.79,75.44 ; SW2.3 59.94,75.44 ; SW2.3 61.37,74.02
  vias: v1(14.8,75.98) v1(14.8,75.47) v1(15.3,75.98) v1(15.3,75.47) v1(15.81,75.98) v1(15.81,75.47)
VSADJ: length 33.3
  TOP w0.203: J8.2 66.38,21.88 57.61,21.88 46.2,33.29 U1.22
X1: length 3.5
  TOP w0.203: U7.27 26.47,77.98 26.37,78.08 C51.1 26.37,79.16 26.33,79.2 Y1.3
